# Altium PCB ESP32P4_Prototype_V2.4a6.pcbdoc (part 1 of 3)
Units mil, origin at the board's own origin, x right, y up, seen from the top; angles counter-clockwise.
Board outline 8474.8 x 7265.9 mil, 6 copper layers (Top Layer, GND, VCC, VCC1, GND1, Bottom Layer), stack 62.3 mil thick; 189 components, 155 nets, 775 pads, 406 vias.
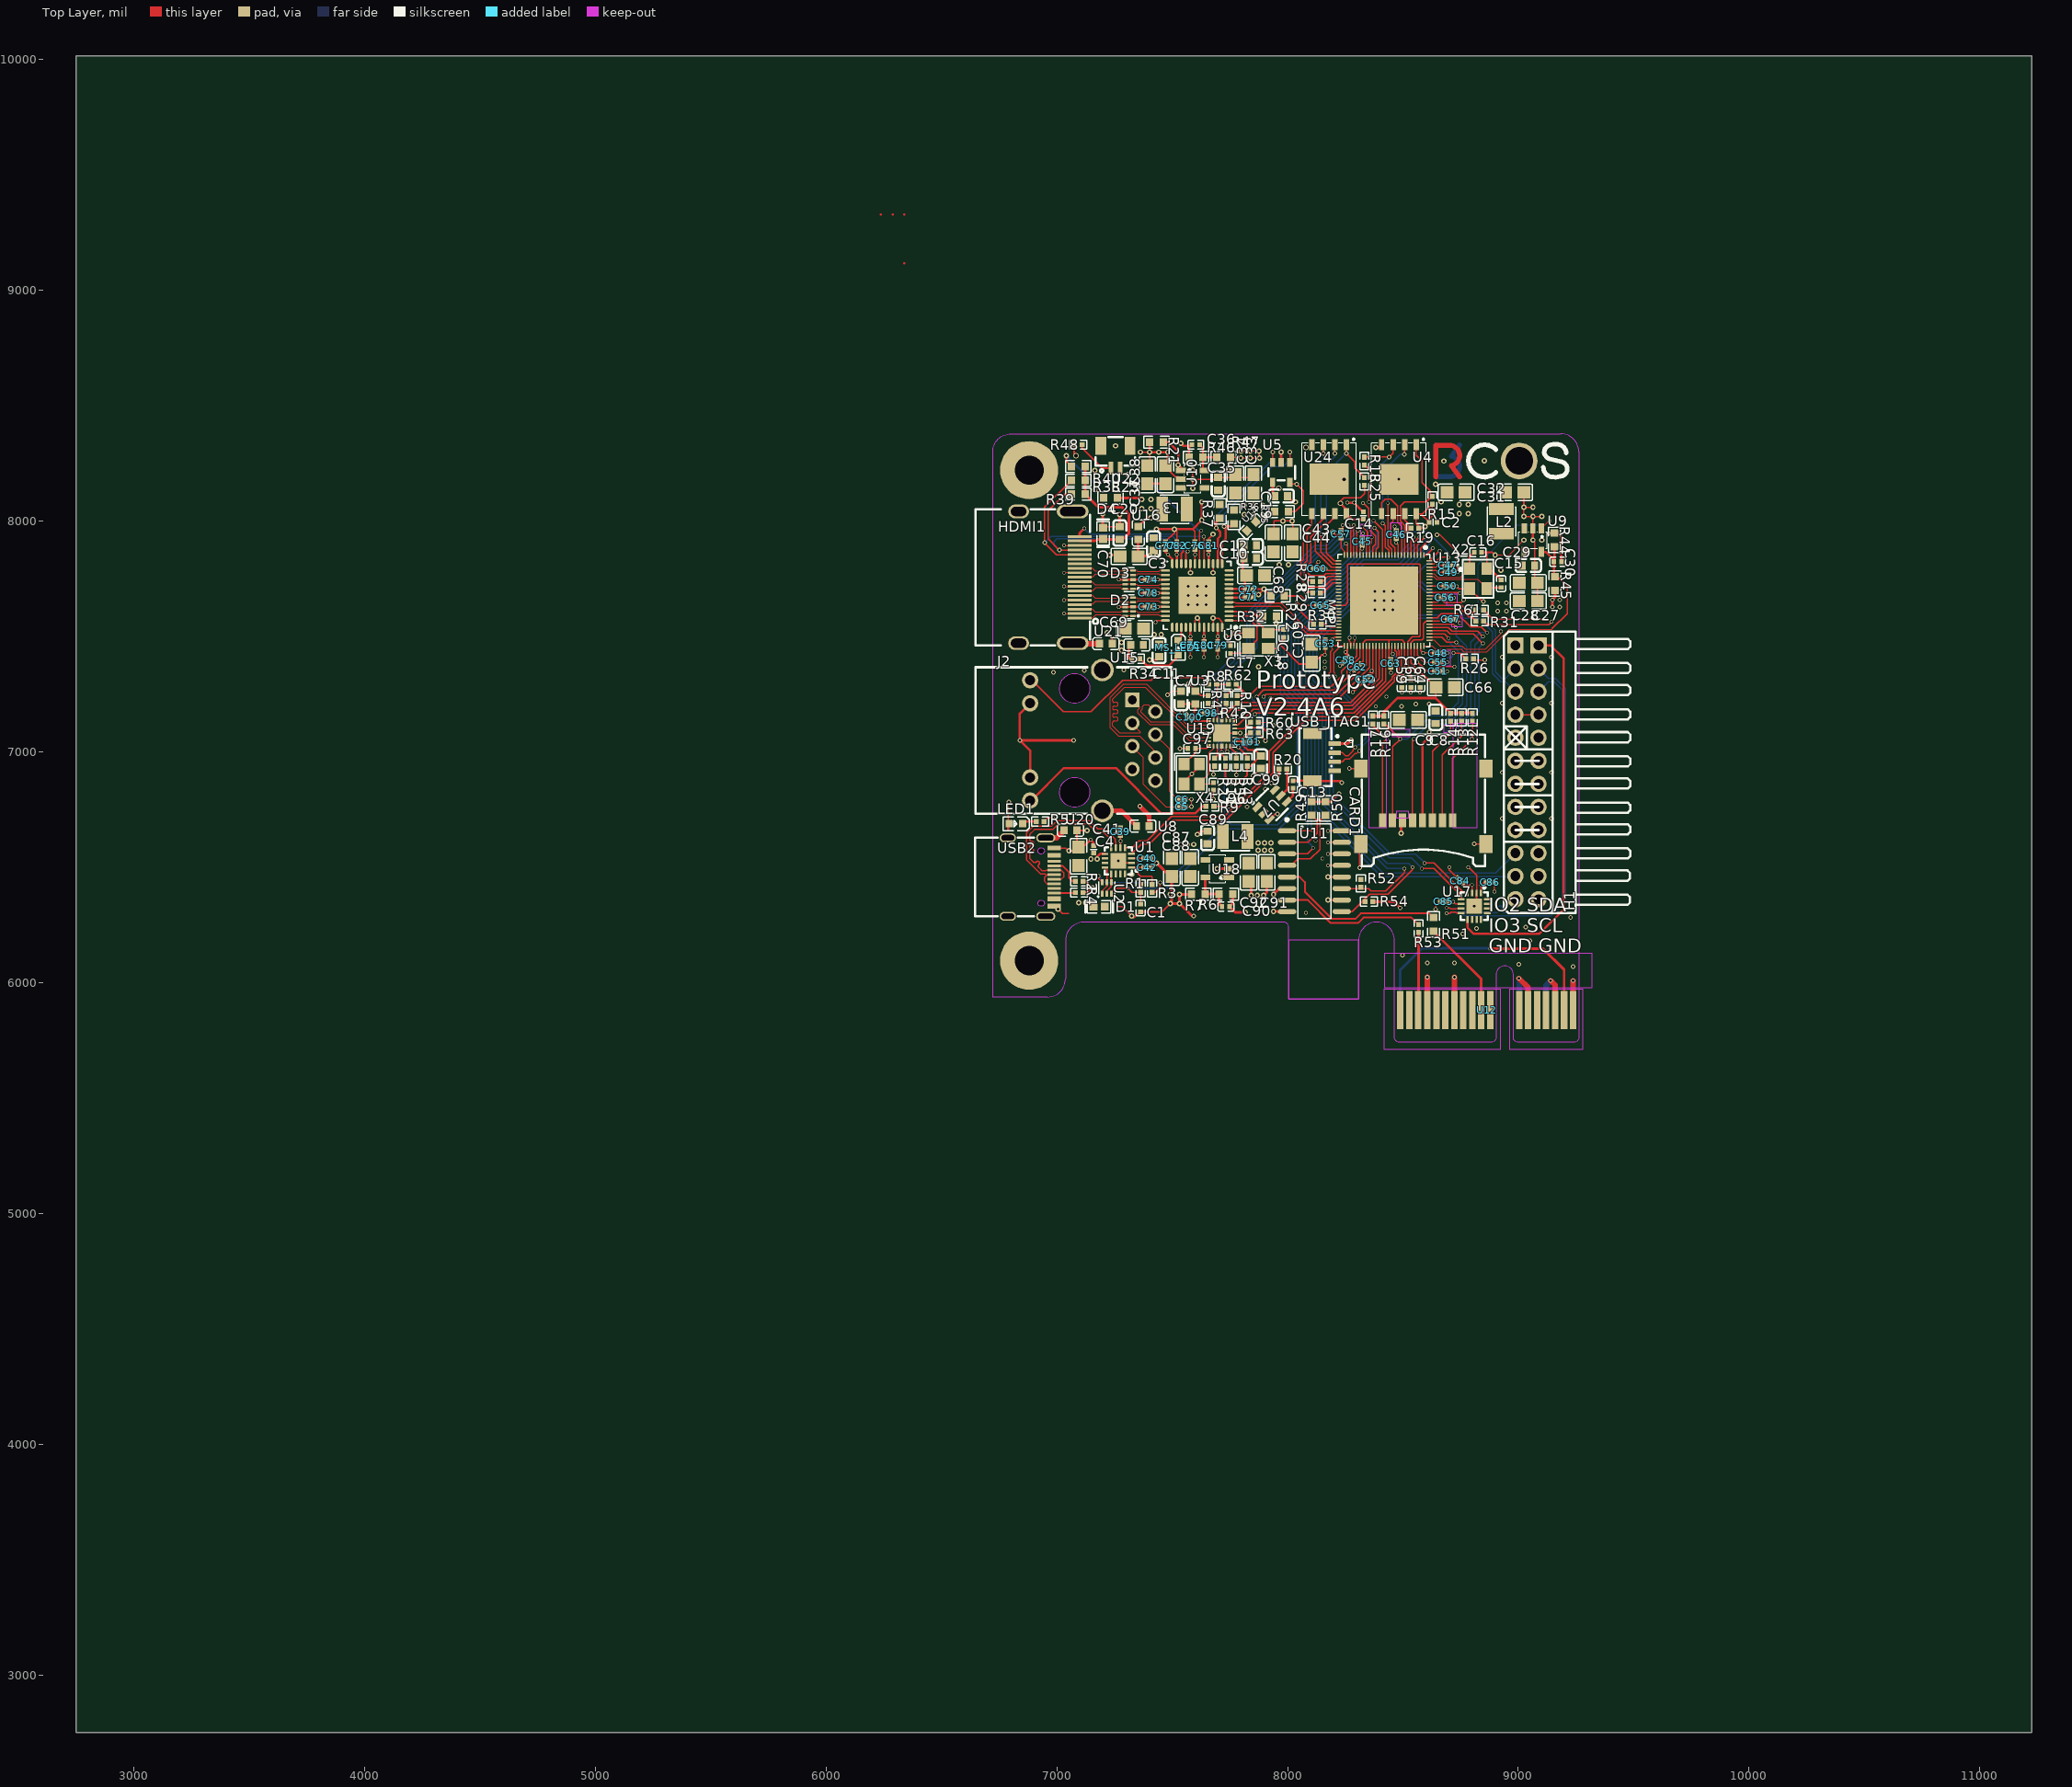
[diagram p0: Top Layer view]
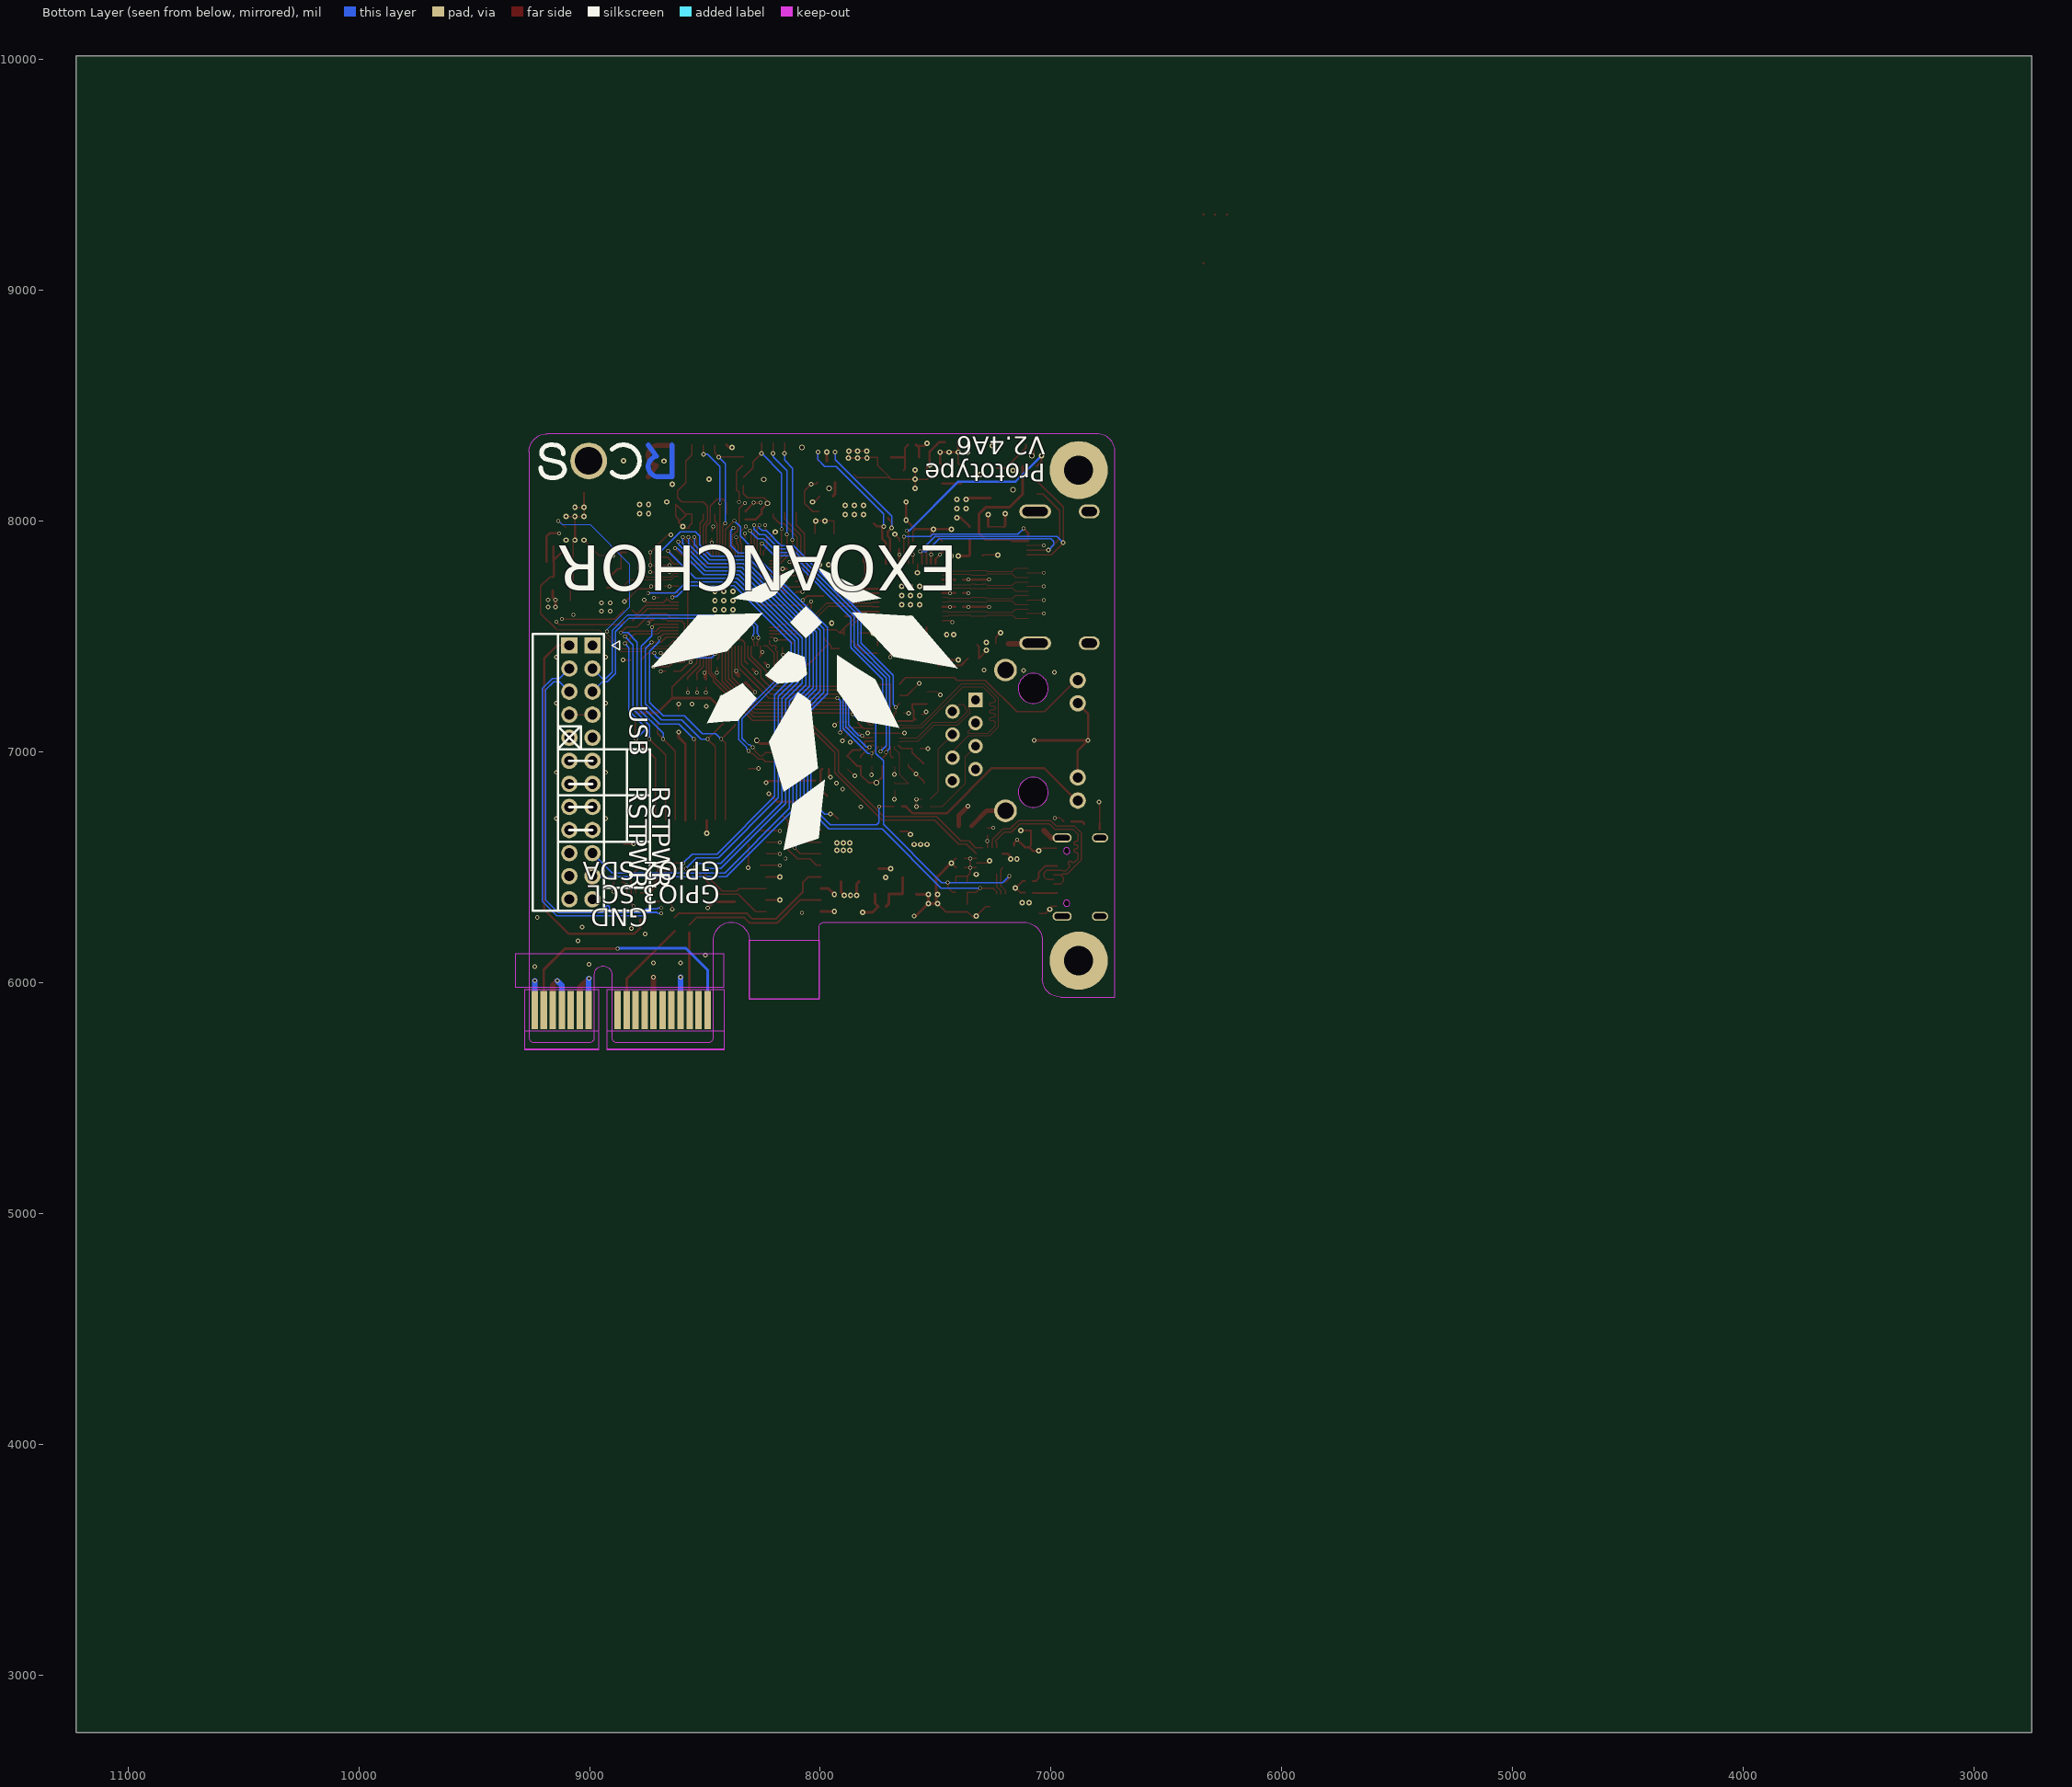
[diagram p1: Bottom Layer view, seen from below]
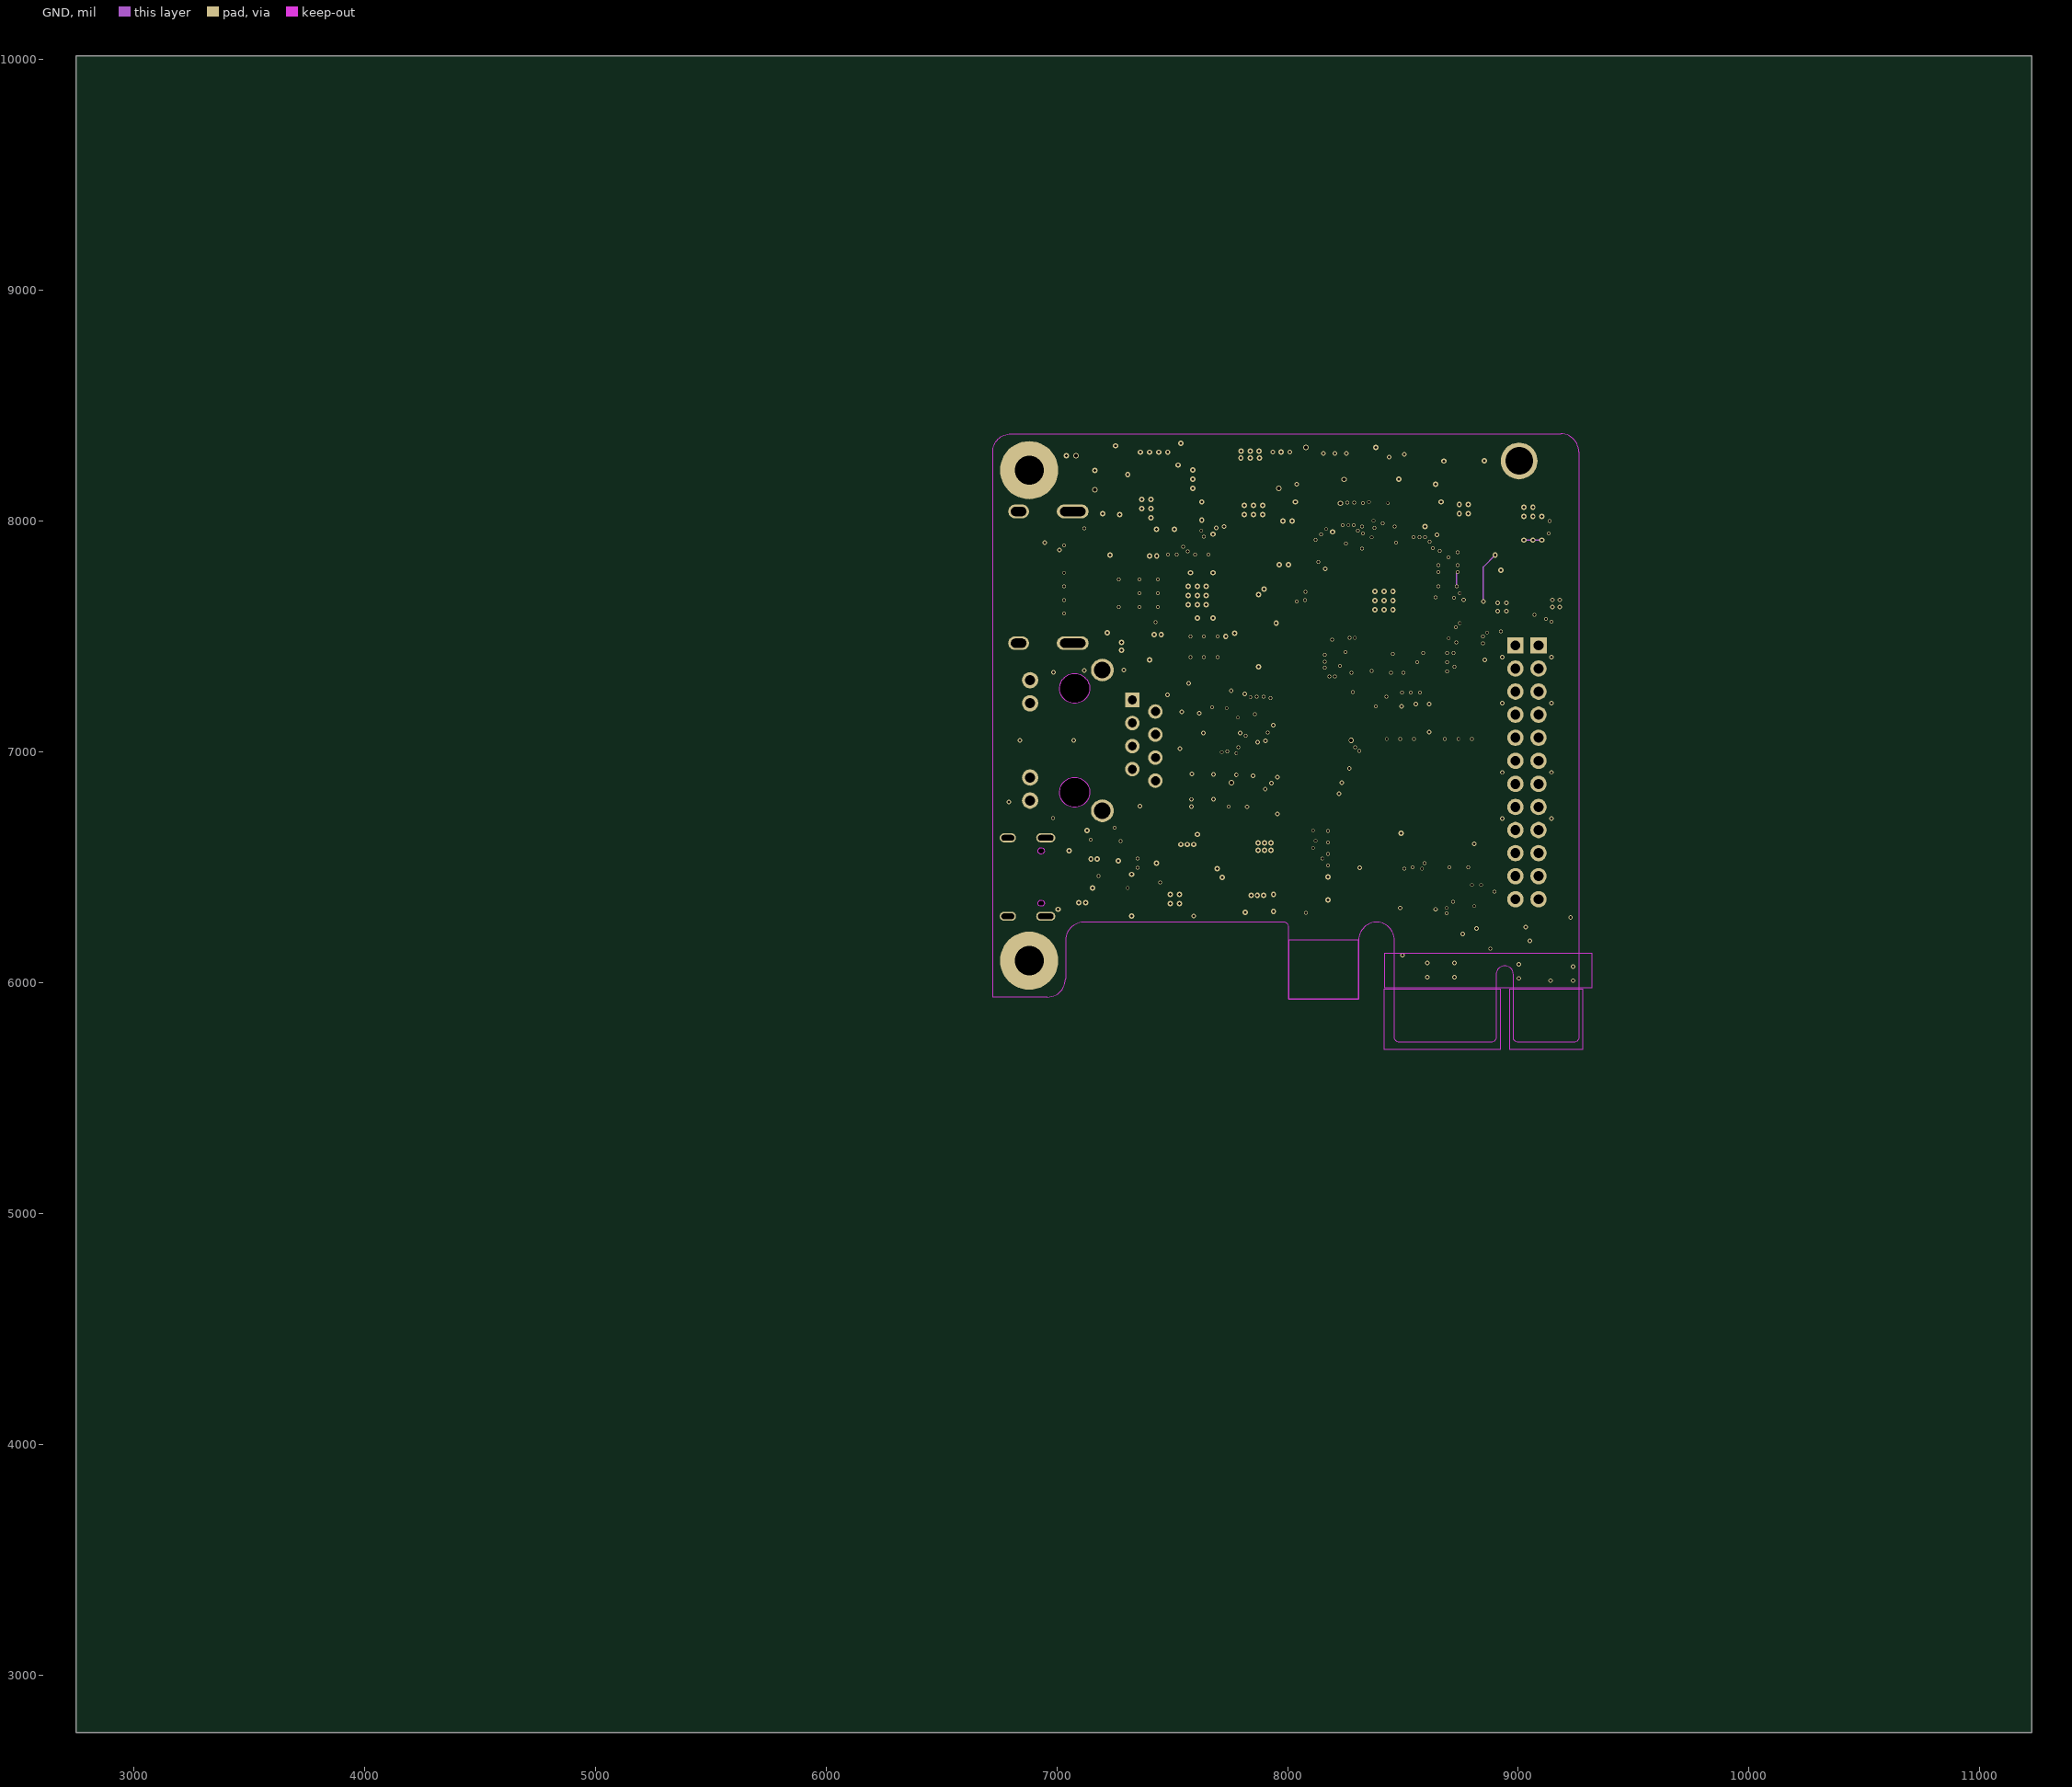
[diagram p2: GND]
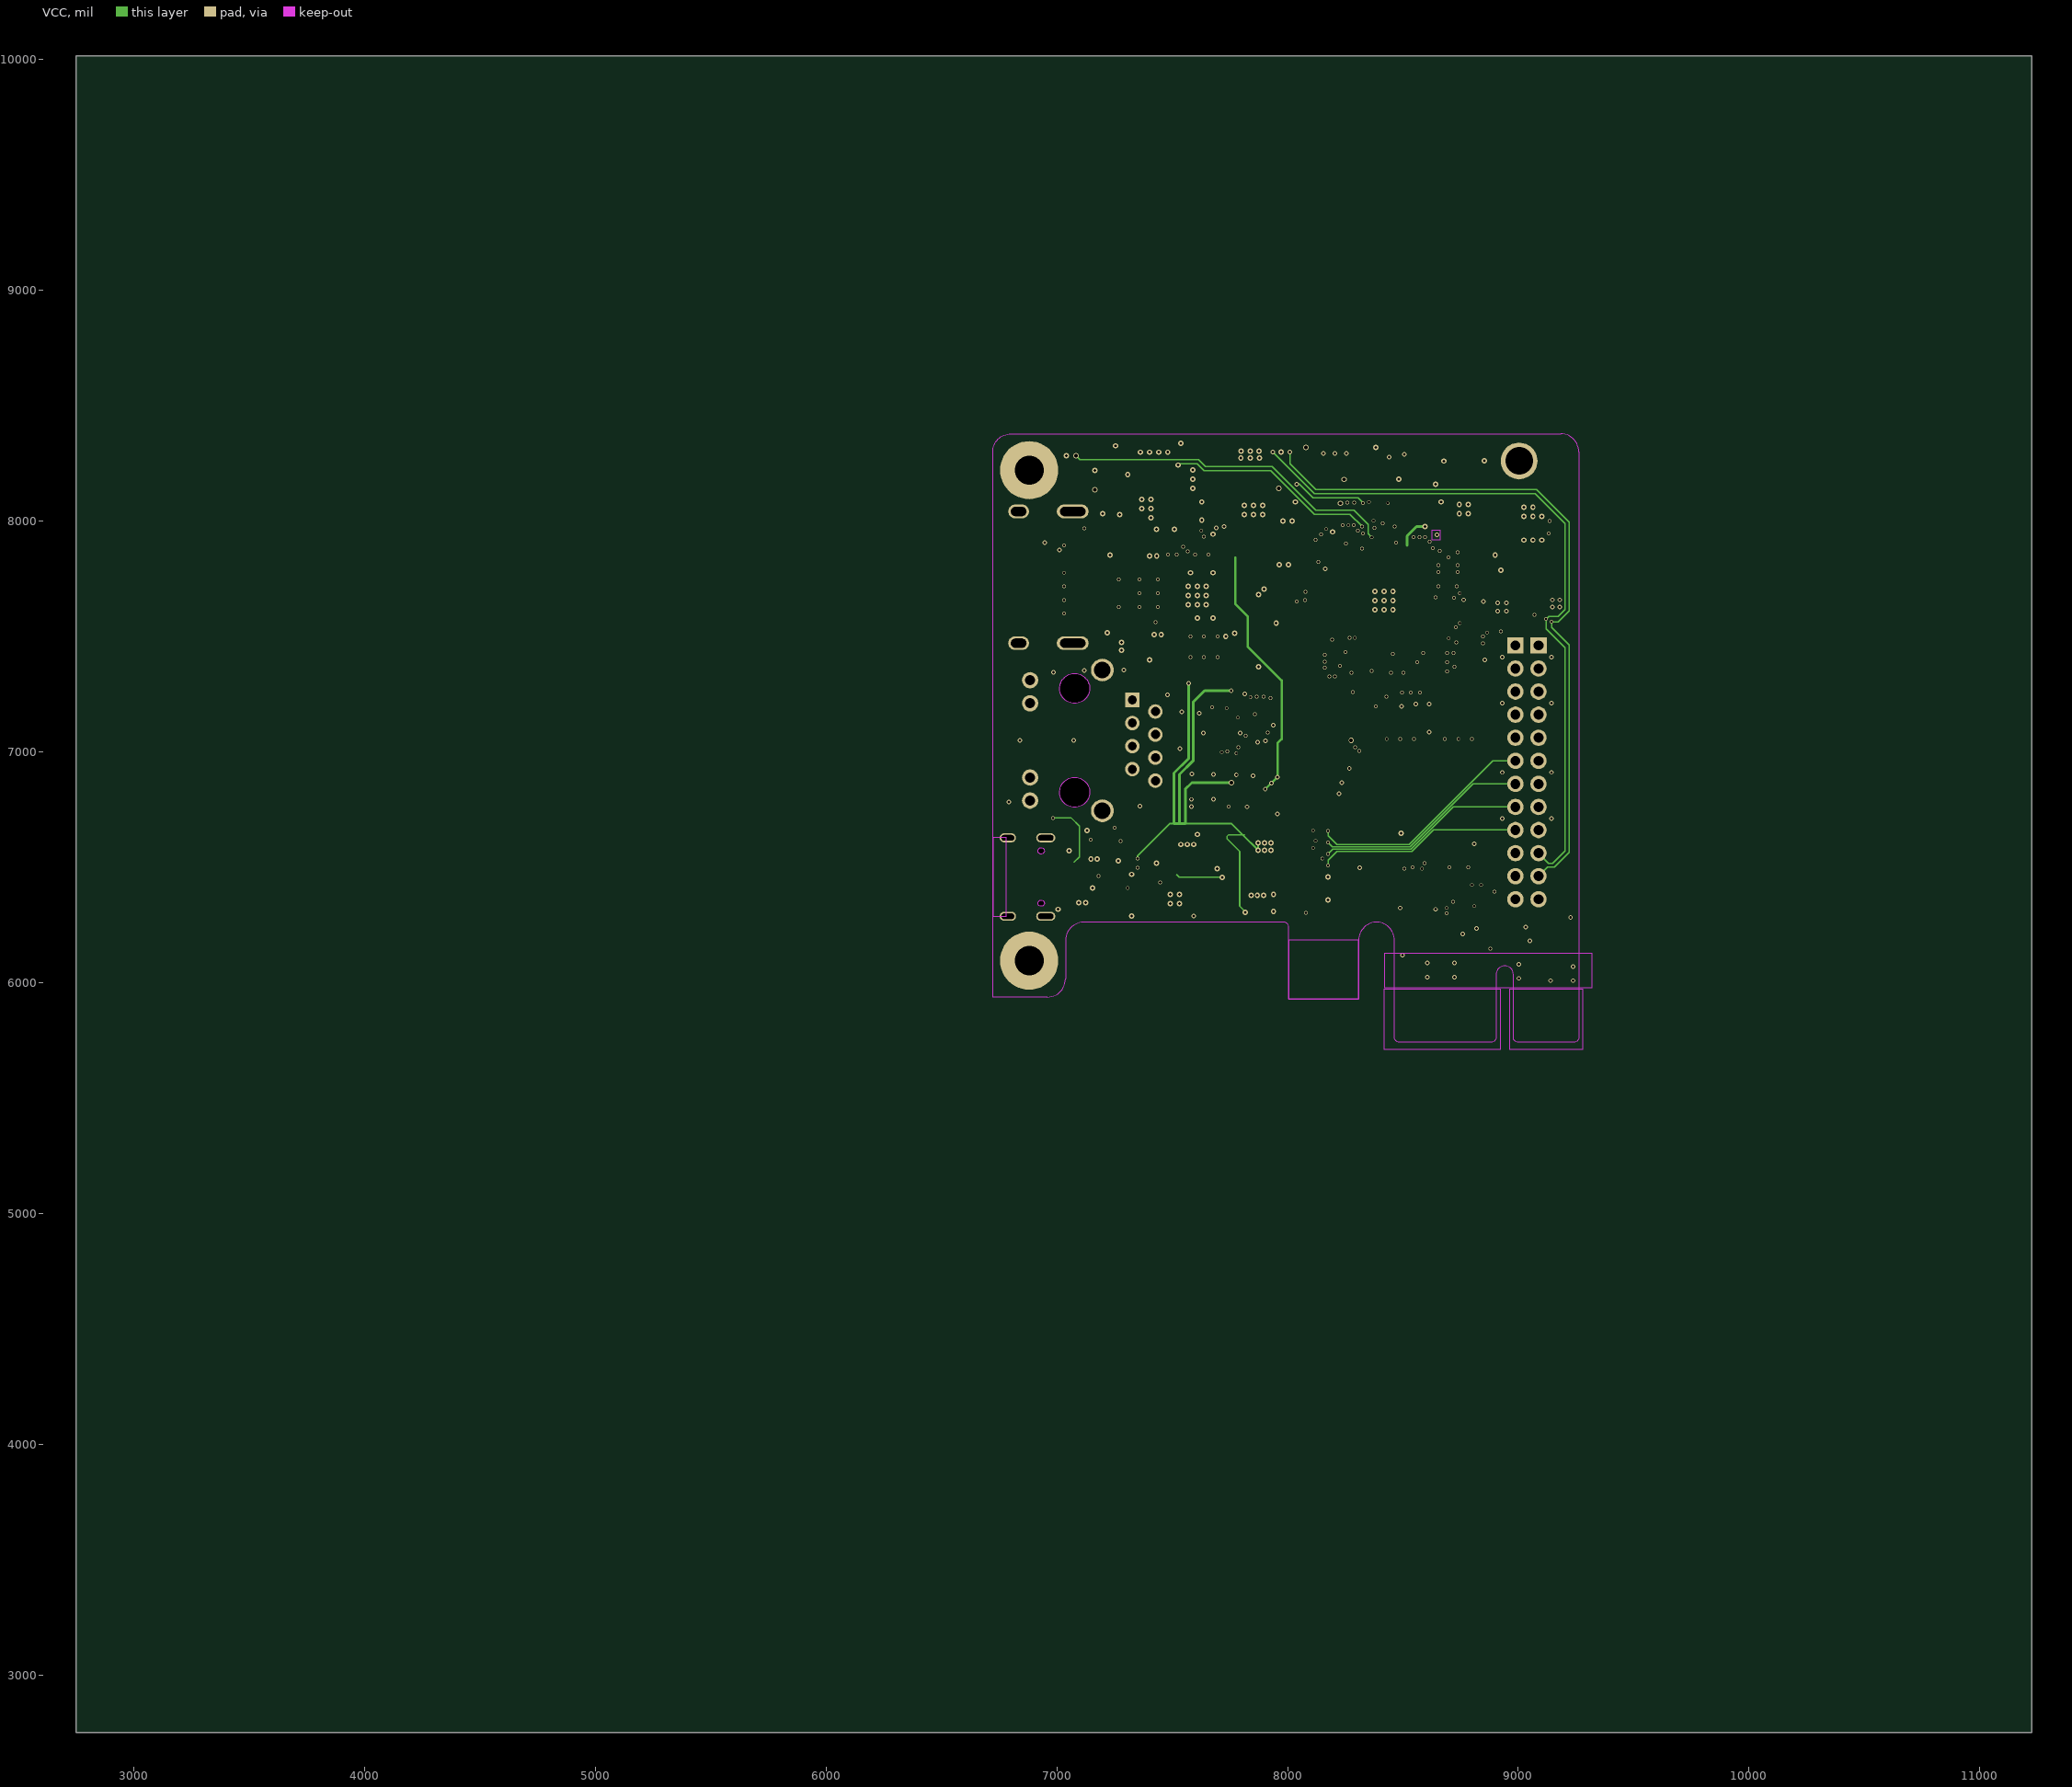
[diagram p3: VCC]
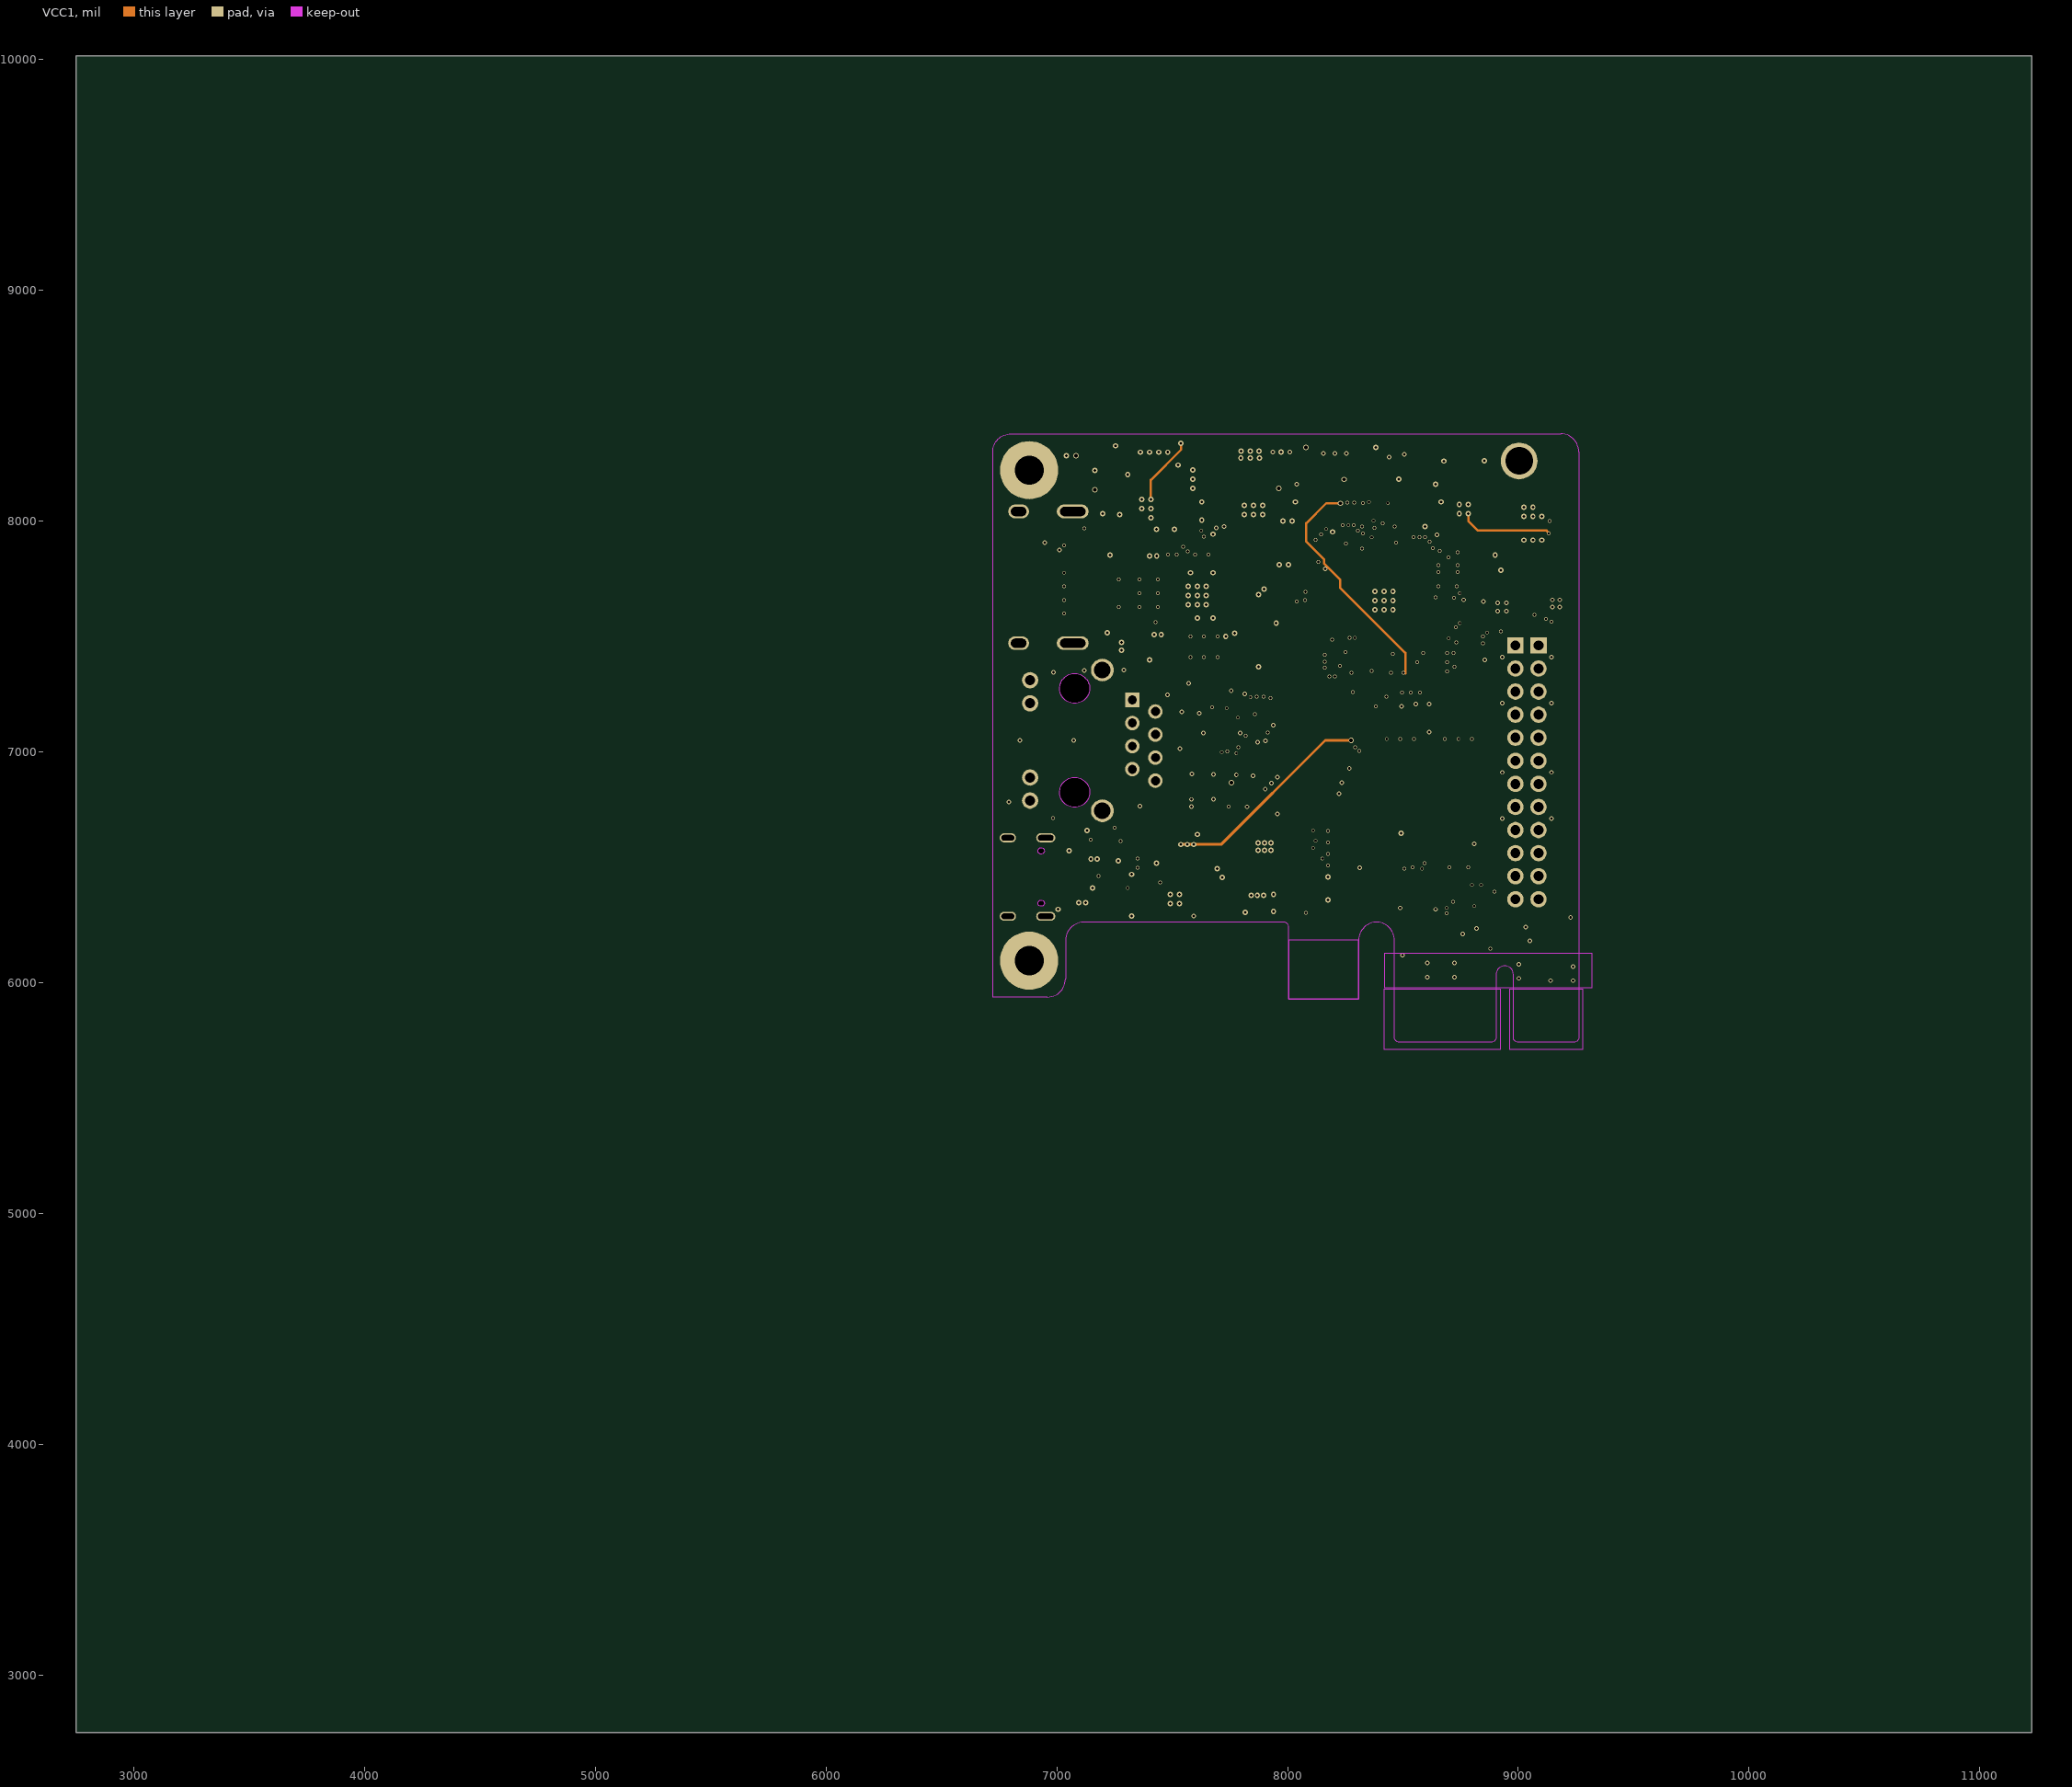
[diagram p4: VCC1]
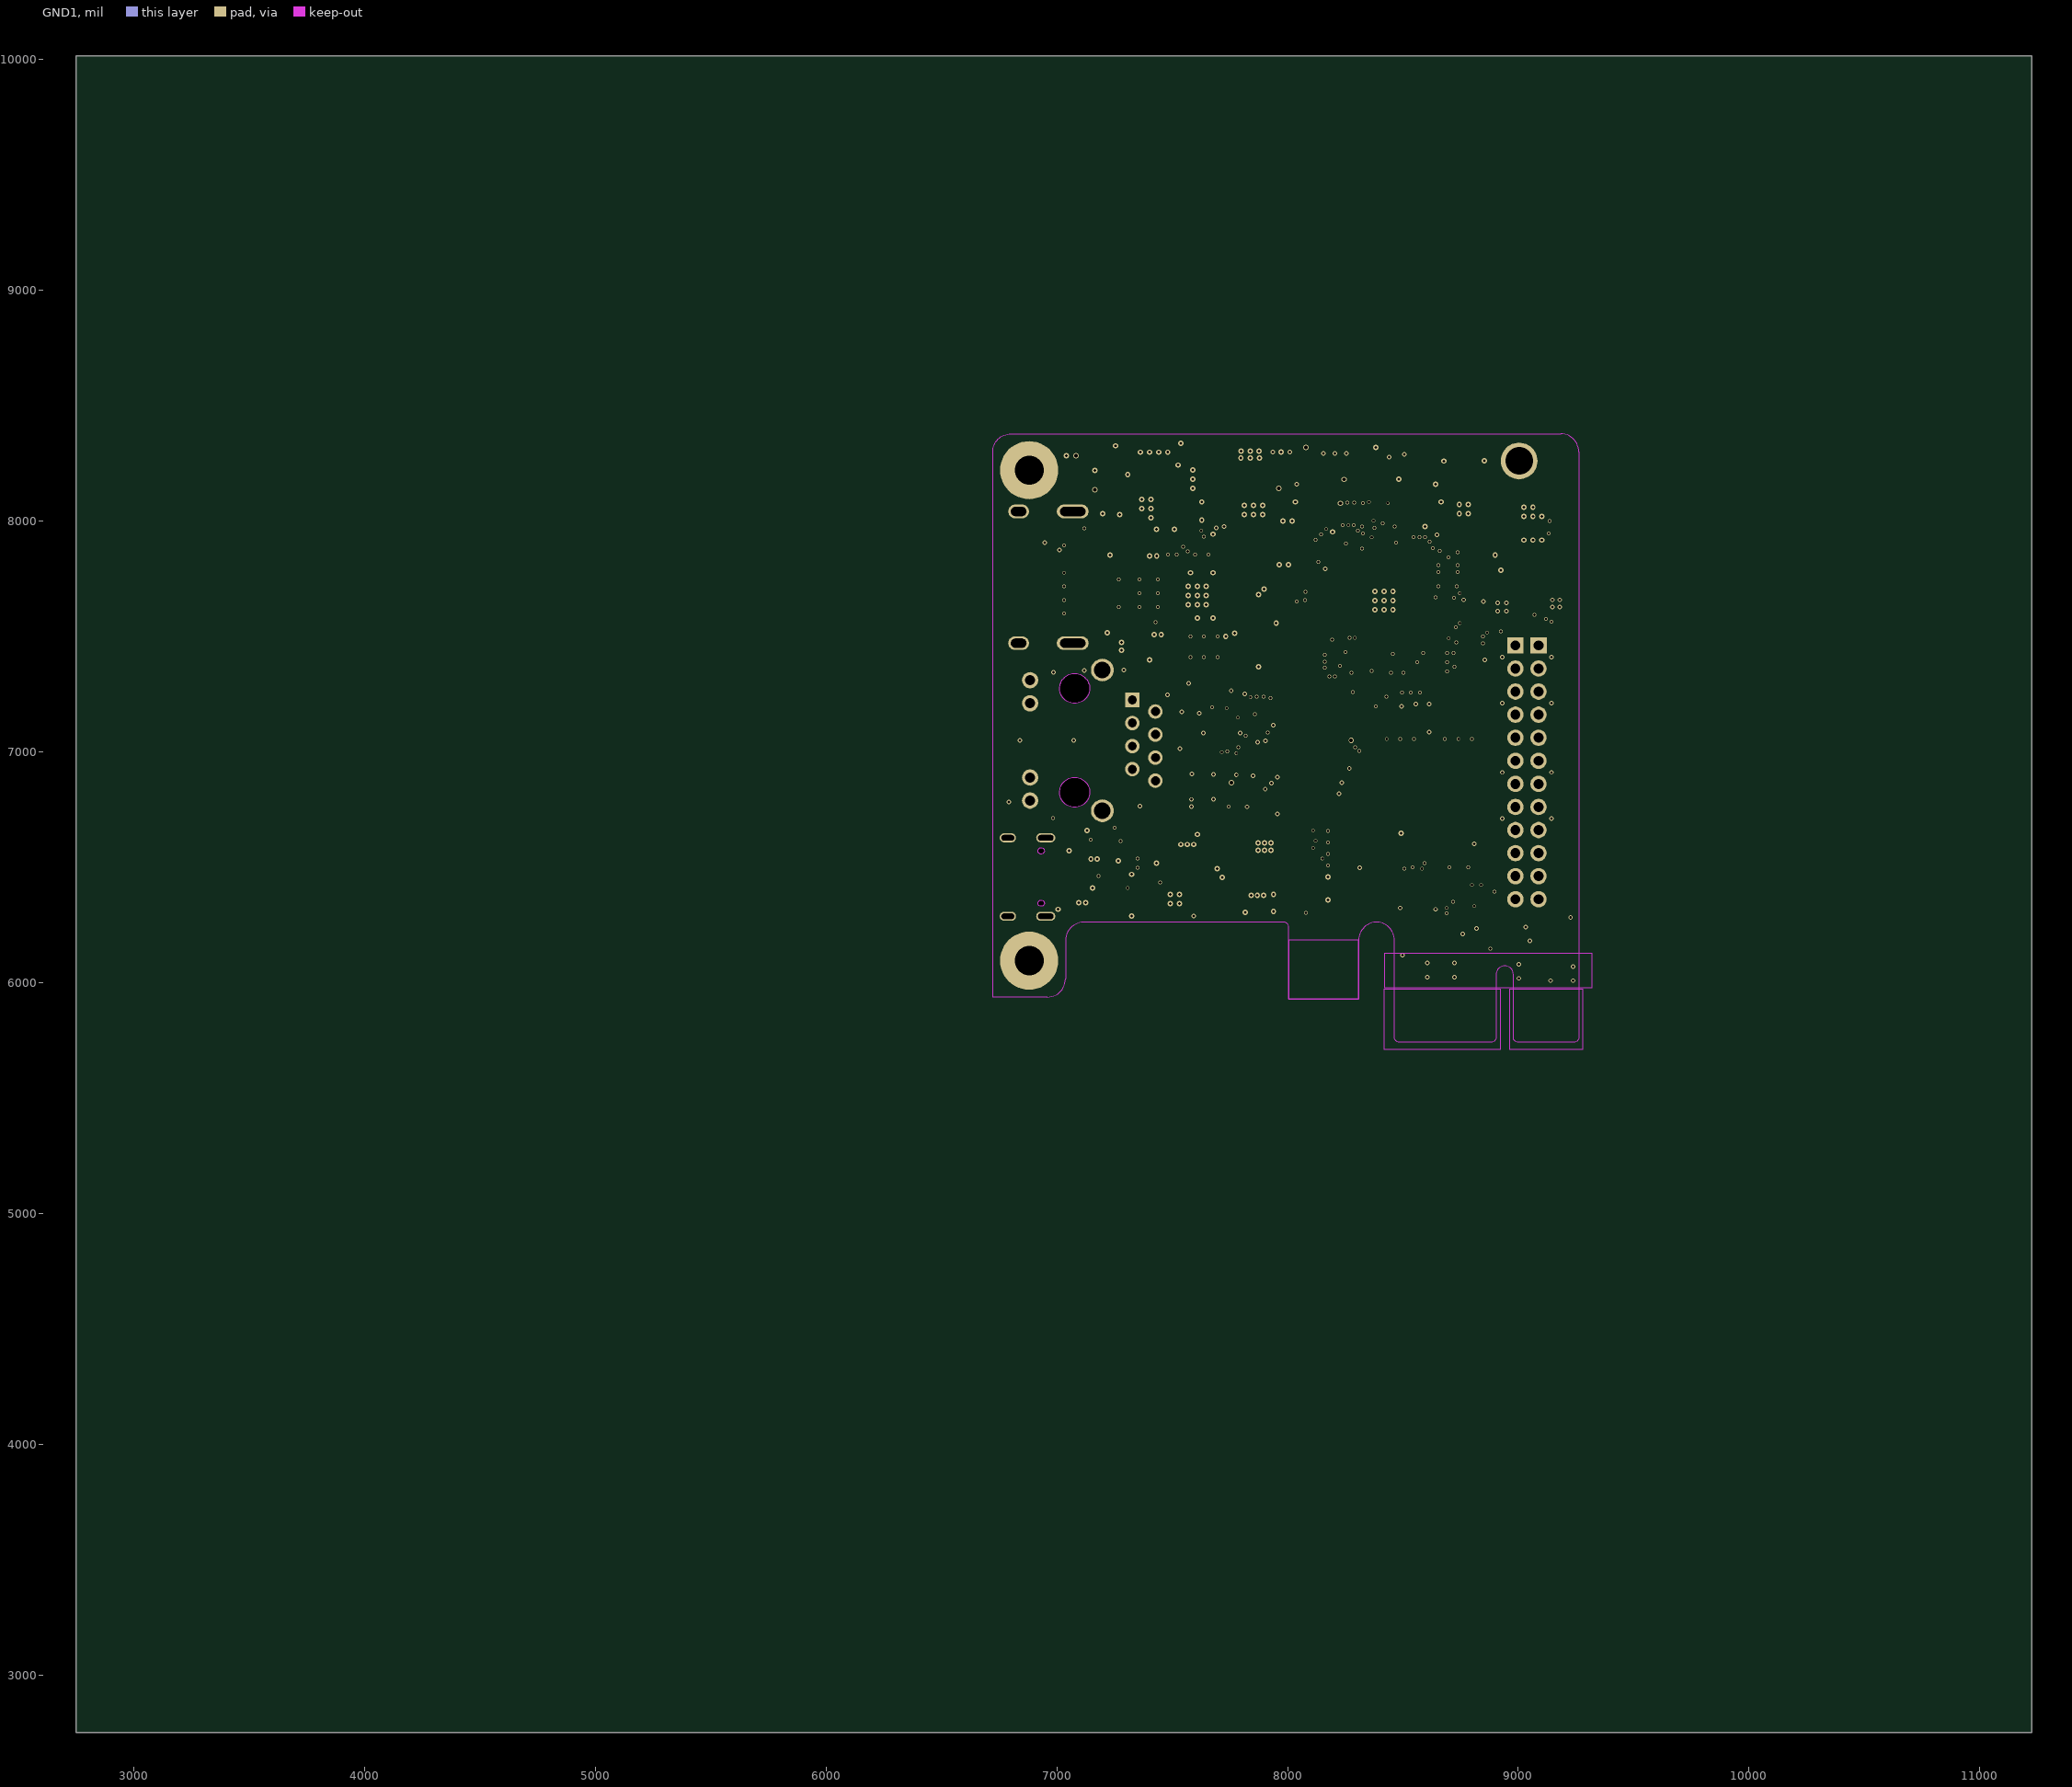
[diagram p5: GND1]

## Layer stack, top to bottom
Top Layer: signal copper 1.4
Dielectric1: surface 3.9, 3313 RC57% 4.2mil, Dk 0
GND: signal copper 1.4
Dielectric2: surface 21.7, 0.55mm H/H No copper, Dk 0
VCC: signal copper 1.4
Dielectric3: surface 4.3, 2116 RC54% 4.9mil, Dk 0
VCC1: signal copper 0.6
Dielectric4: surface 21.7, 0.55mm H/H No copper, Dk 0
GND1: signal copper 0.6
Dielectric5: surface 3.9, 3313 RC57% 4.2mil, Dk 0
Bottom Layer: signal copper 1.4

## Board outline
11224.8,2750 2750,2750 2750,10015.9 11224.8,10015.9

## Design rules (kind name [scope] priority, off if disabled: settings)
BoardOutlineClearance copperThickness1oz [All] p0: genericclearance=10 ignorepadtopadclearanceinfootprint=FALSE except(0: Arc-SplitContinuation Track-SplitContinuation SMDPad-SplitContinuation THPad-SplitContinuation Via-SplitContinuation Fill-SplitContinuation Poly-SplitContinuation Region-SplitContinuation Text-SplitContinuation)
BoardOutlineClearance copperThickness2oz [All] p0: genericclearance=10 ignorepadtopadclearanceinfootprint=FALSE except(0: Arc-SplitContinuation Track-SplitContinuation SMDPad-SplitContinuation THPad-SplitContinuation Via-SplitContinuation Fill-SplitContinuation Poly-SplitContinuation Region-SplitContinuation Text-SplitContinuation)
BoardOutlineClearance copperThicknessInner0.5oz [All] p0: genericclearance=10 ignorepadtopadclearanceinfootprint=FALSE except(0: Arc-SplitContinuation Track-SplitContinuation SMDPad-SplitContinuation THPad-SplitContinuation Via-SplitContinuation Fill-SplitContinuation Poly-SplitContinuation Region-SplitContinuation Text-SplitContinuation)
BoardOutlineClearance Copper_1 [All] p0: genericclearance=10 ignorepadtopadclearanceinfootprint=FALSE except(0: Arc-SplitContinuation Track-SplitContinuation SMDPad-SplitContinuation THPad-SplitContinuation Via-SplitContinuation Fill-SplitContinuation Poly-SplitContinuation Region-SplitContinuation Text-SplitContinuation)
BoardOutlineClearance Copper_copperRegion [All] p0: genericclearance=10 ignorepadtopadclearanceinfootprint=FALSE except(0: Arc-SplitContinuation Track-SplitContinuation SMDPad-SplitContinuation THPad-SplitContinuation Via-SplitContinuation Fill-SplitContinuation Poly-SplitContinuation Region-SplitContinuation Text-SplitContinuation)
BoardOutlineClearance Plane_innerPlane [All] p0: genericclearance=10 ignorepadtopadclearanceinfootprint=FALSE except(0: Arc-SplitContinuation Track-SplitContinuation SMDPad-SplitContinuation THPad-SplitContinuation Via-SplitContinuation Fill-SplitContinuation Poly-SplitContinuation Region-SplitContinuation Text-SplitContinuation)
BoardOutlineClearance otherClearance [All] p0: genericclearance=10 ignorepadtopadclearanceinfootprint=FALSE except(0: Arc-SplitContinuation Track-SplitContinuation SMDPad-SplitContinuation THPad-SplitContinuation Via-SplitContinuation Fill-SplitContinuation Poly-SplitContinuation Region-SplitContinuation Text-SplitContinuation)
Clearance copperThickness1oz [All] p1: gap=7 ignorepadtopadclearanceinfootprint=FALSE
Clearance copperThickness2oz [All] p1: gap=7 ignorepadtopadclearanceinfootprint=FALSE
Clearance copperThicknessInner0.5oz [All] p1: gap=7 ignorepadtopadclearanceinfootprint=FALSE
Clearance Copper_1 [All] p1: gap=7 ignorepadtopadclearanceinfootprint=FALSE
Clearance Copper_copperRegion [All] p1: gap=7 ignorepadtopadclearanceinfootprint=FALSE
Clearance Plane_innerPlane [All] p1: gap=7 ignorepadtopadclearanceinfootprint=FALSE
Clearance otherClearance [All] p1: gap=7 ignorepadtopadclearanceinfootprint=FALSE
DiffPairsRouting differentialPair [All] p1: maxuncoupledlength=10 minlimit=5.9843 maxlimit=Infinity mostfreqgap=8 toplayer_minwidth=4 toplayer_prefwidth=4.7 toplayer_maxwidth=10 bottomlayer_minwidth=4 bottomlayer_prefwidth=4.7 bottomlayer_maxwidth=10 midlayer1_minwidth=4 midlayer1_prefwidth=4.7 midlayer1_maxwidth=10 midlayer2_minwidth=4 midlayer2_prefwidth=4.7 midlayer2_maxwidth=10 midlayer3_minwidth=4 midlayer3_prefwidth=4.7 midlayer3_maxwidth=10 midlayer4_minwidth=4 midlayer4_prefwidth=4.7 midlayer4_maxwidth=10
PasteMaskExpansion pasteMaskExpansion [All] p1: expansion=0
PlaneConnect innerPlane [All] p1: planeconnectstyle=Relief reliefexpansion=20 reliefentries=4 reliefconductorwidth=10 reliefairgap=10
PolygonConnect 1 [All] p1: connectstyle=Direct reliefentries=4 reliefconductorwidth=10 polygonreliefangle="90 Angle" airgapwidth=10
PolygonConnect copperRegion [All] p1: connectstyle=Direct reliefentries=4 reliefconductorwidth=10 polygonreliefangle="90 Angle" airgapwidth=10
RoutingVias viaSize [All] p1: viastyle="Through Hole" holewidth=12.0078 minholewidth=7.874 maxholewidth=248.0316 width=12.0078 minwidth=7.874 maxwidth=248.0316
SolderMaskExpansion solderMaskExpansion [IsVia] p1: useseparateexpansions=TRUE expansion=-1000 expansionbottom=-1000
SolderMaskExpansion solderMaskExpansion [All] p2: useseparateexpansions=TRUE expansion=2.0079 expansionbottom=2.0079
Width copperThickness1oz [All] p1: maxlimit=100 minlimit=4 preferedwidth=10
Width copperThickness0.5oz [All] p1: maxlimit=100 minlimit=4 preferedwidth=10
Width copperThickness2oz [All] p1: maxlimit=100 minlimit=8 preferedwidth=10

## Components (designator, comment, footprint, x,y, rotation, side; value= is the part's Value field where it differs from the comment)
C1 "1uF" C0402#1 7362.6,6323.7 r90 top
C2 "100nF" "C0402 去耦电容"#1 8630.5,7995.3 r0 top
C3 "1uF" C0603#1 7419.4,7900.4 r270 top
C4 "4.7uF" C0805#1 7094.6,6548 r90 top
C5 "100nF" "C0402 去耦电容"#1 7541.5,6762.5 r180 top
C6 "100nF" "C0402 去耦电容"#1 7541.5,6794 r180 top
C7 "1uF" C0603#2 7538.5,7235.5 r270 top
C8 "100nF" C0603#1 8641.9,7150.4 r270 top
C9 "10uF" C0805#2 8523.8,7138.5 r0 top
C10 "1uF" C0603#2 7837.7,7839 r180 top
C11 "1uF" C0603#1 7443.1,7439.7 r90 top
C12 "1uF" C0603#2 7837.7,7894.9 r180 top
C13 "1nF" C0402#1 8023.7,6858.4 r270 top
C14 "100nF" "C0402 去耦电容"#1 8328.9,8024.4 r90 top
C15 "22pF" C0402#1 8925.3,7729.1 r90 top
C16 "22pF" C0402#2 8825,7864.9 r180 top
C17 "22pF" C0402#1 7752.6,7443.7 r90 top
C18 "22pF" C0402#1 7982.6,7513.7 r270 top
C19 "100nF" C0603#2 7972.6,8109 r180 top
C20 "100nF" C0603#2 7272.6,7948.7 r270 top
C27 "10uF" C0805#1 9043.5,7654.2 r180 top
C28 "10uF" C0805#1 9043.5,7732.9 r180 top
C29 "100nF" C0603#2 9043.5,7807.7 r180 top
C30 "22pF" C0402#1 9171.1,7824.1 r0 top
C31 "10uF" C0805#1 8984.4,8124.8 r180 top
C32 "10uF" C0805#2 8730.5,8124.8 r0 top
C33 "10uF" C0805#3 7852.5,8162.2 r270 top
C34 "10uF" C0805#3 7773.8,8162.2 r270 top
C35 "100nF" C0603#1 7699,8162.2 r270 top
C36 "22pF" C0402#3 7602.5,8331.5 r180 top
C37 "10uF" C0805#2 7470.6,8201.5 r270 top
C38 "10uF" C0805#2 7391.9,8201.5 r270 top
C39 "100nF" "C0402 去耦电容"#2 7275.7,6654.3 r270 top
C40 "100nF" "C0402 去耦电容"#3 7391.9,6538.2 r180 top
C41 "100nF" "C0402 去耦电容"#1 7159.6,6577.5 r270 top
C42 "100nF" "C0402 去耦电容"#3 7391.9,6498.8 r180 top
C43 "10uF" C0805#3 8021.8,7906.3 r270 top
C44 "10uF" C0805#3 7939.1,7906.3 r270 top
C45 "100nF" "C0402 去耦电容"#3 8323,7912.2 r270 top
C46 "100nF" "C0402 去耦电容"#2 8470.6,7941.7 r270 top
C47 "100nF" "C0402 去耦电容"#3 8697.3,7808.7 r180 top
C48 "100nF" "C0402 去耦电容"#2 8652.6,7428.1 r180 top
C49 "100nF" "C0402 去耦电容"#3 8697.3,7779.2 r180 top
C50 "100nF" "C0402 去耦电容"#1 8693.3,7718.2 r180 top
C51 "100nF" "C0402 去耦电容"#2 8652.6,7349.4 r180 top
C52 "100nF" "C0402 去耦电容"#2 8337.6,7313.7 r45 top
C53 "100nF" "C0402 去耦电容"#1 8163.5,7469.3 r90 top
C55 "100nF" "C0402 去耦电容"#2 8652.6,7388.7 r180 top
C56 "100nF" "C0402 去耦电容"#2 8682.6,7668.7 r180 top
C57 "100nF" "C0402 去耦电容"#2 8232.6,7943.7 r270 top
C58 "100nF" "C0402 去耦电容"#2 8252.1,7398.4 r45 top
C59 "1uF" C0402#2 8495.5,7296 r90 top
C60 "100nF" "C0402 去耦电容"#2 8128.1,7794.1 r0 top
C61 "1uF" C0402#2 8534.9,7296 r90 top
C62 "100nF" "C0402 去耦电容"#2 8302.6,7368.7 r45 top
C63 "100nF" "C0402 去耦电容"#2 8447.6,7383.7 r90 top
C64 "1uF" C0402#2 8574.2,7296 r90 top
C65 "100nF" "C0402 去耦电容"#1 8142.2,7635.5 r0 top
C66 "10uF" C0805#2 8683.2,7280.3 r180 top
C67 "100nF" "C0402 去耦电容"#1 8707.3,7574.8 r180 top
C68 "4.7uF" C0805#1 7861.3,7765.1 r180 top
C69 "10uF" C0805#2 7336.8,7534.2 r0 top
C70 "4.7uF" C0805#3 7313.1,7847.2 r0 top
C71 "100nF" "C0402 去耦电容"#2 7832.6,7670 r180 top
C72 "100nF" "C0402 去耦电容"#3 7832.1,7705.5 r180 top
C73 "100nF" "C0402 去耦电容"#2 7397.6,7628.7 r0 top
C74 "100nF" "C0402 去耦电容"#1 7397.8,7746.8 r0 top
C75 "100nF" "C0402 去耦电容"#3 7578.9,7461.4 r90 top
C76 "100nF" "C0402 去耦电容"#1 7598.6,7894.4 r270 top
C77 "100nF" "C0402 去耦电容"#1 7470.6,7894.4 r270 top
C78 "100nF" "C0402 去耦电容"#1 7397.8,7687.8 r0 top
C79 "100nF" "C0402 去耦电容"#3 7697,7461.4 r90 top
C80 "100nF" "C0402 去耦电容"#3 7637.9,7461.4 r90 top
C81 "100nF" "C0402 去耦电容"#1 7657.6,7894.4 r270 top
C82 "100nF" "C0402 去耦电容"#1 7519.8,7894.4 r270 top
C84 "100nF" "C0402 去耦电容"#2 8748.2,6441.7 r315 top
C85 "100nF" "C0402 去耦电容"#3 8677.3,6351.1 r0 top
C86 "100nF" "C0402 去耦电容"#2 8878.1,6435.8 r180 top
C87 "4.7uF" C0805#3 7498.1,6498.7 r90 top
C88 "4.7uF" C0805#3 7578.1,6498.7 r90 top
C89 "100nF" C0603#3 7653.1,6628.7 r270 top
C90 "22pF" C0402#2 7732.4,6329.5 r0 top
C91 "10uF" C0805#1 7831.5,6478.2 r90 top
C92 "10uF" C0805#1 7910.2,6478.2 r90 top
C96 "22pF" C0402#2 7678.9,6850.7 r270 top
C97 "22pF" C0402#3 7584.8,7014.5 r0 top
C98 "100nF" "C0402 去耦电容"#1 7655.8,7167.9 r0 top
C99 "1uF" C0603#3 7883.9,6955.5 r90 top
C100 "100nF" "C0402 去耦电容"#4 7573.9,7150.7 r315 top
C101 "100nF" "C0402 去耦电容"#3 7825,7042.1 r180 top
C109 "10uF" C0805#1 8104.5,7427.9 r90 top
CARD1 "XKTF-1307-18" TF-SMD_XKTF-1307-18 8588.7,6764.5 r0 top
D1 "SLPESD0603M05" D0603-BI#1 7183.2,6329.5 r180 top
D2 "TPD4E05U06DQAR" USON-10_L2.5-W1.0-P0.50-BL#1 7313.2,7628.7 r90 top
D3 "TPD4E05U06DQAR" USON-10_L2.5-W1.0-P0.50-BL#2 7313.2,7746.8 r90 top
D4 "SLPESD0603M05" D0603-BI#2 7200.9,7947.6 r270 top
H1 "X6521WR-2x12H-C60D30" HDR-TH_24P-P2.54-H-M-R2-C12-S2.54 9037.6,6911.4 r90 top
HDMI1 "HDMI-001S" HDMI-SMD_HDMI-001S 6966.7,7756.7 r270 top
J2 "HR911105A" RJ45-TH_HR911105A 7155.7,7050 r270 top
L2 "2.2uH" IND-SMD_L3.0-W3.0_FNR30XXS#1 8927,7998.8 r270 top
L3 "2.2uH" IND-SMD_L3.0-W3.0_FNR30XXS#2 7510,8051.9 r0 top
L4 "2.2uH" IND-SMD_L3.0-W3.0_FNR30XXS#2 7773.1,6633.7 r180 top
LED1 "NCD0603R1" LED0603-RD_RED#1 6822.6,6688.7 r180 top
MS_LED1 "NCD0603R1" LED0603-RD_RED#2 7525.7,7451.5 r270 top
R1 "10kΩ" R0402#1 7362.6,6408.7 r270 top
R2 "5.1kΩ" R0402#1 7096.6,6439.7 r180 top
R3 "2.2kΩ" R0402#1 7412.6,6408.7 r270 top
R4 "5.1kΩ" R0402#1 7096.6,6390.5 r180 top
R5 "5.1kΩ" R0402#1 6927.6,6698.7 r180 top
R6 "453kΩ" R0603#1 7733.1,6383.7 r0 top
R7 "100kΩ" R0603#1 7613.1,6383.7 r0 top
R8 "2.2kΩ" R0402#2 7675.8,7292.9 r180 top
R9 "2.2kΩ" R0402#2 7663.9,6763.7 r180 top
R10 "2.49kΩ" R0402#2 7781.6,7227.1 r90 top
R11 "2.2kΩ" R0402#2 7730.5,6955.5 r270 top
R12 "10kΩ" R0402#2 8801.3,7150.4 r270 top
R13 "10kΩ" R0402#2 8754.1,7150.4 r270 top
R14 "10kΩ" R0402#2 8706.8,7150.4 r270 top
R15 "10kΩ" R0402#2 8627.4,8090.9 r90 top
R16 "10kΩ" R0402#3 8417.5,7138.5 r270 top
R17 "10kΩ" R0402#3 8370.2,7138.5 r270 top
R18 "10kΩ" R0402#1 8332.8,8260.6 r90 top
R19 "10kΩ" R0402#3 8551.3,7970.2 r0 top
R20 "22Ω" R0402#2 7980.5,6925.9 r180 top
R21 "100kΩ" R0603#2 7431.3,8343.3 r0 top
R22 "100kΩ" R0603#1 7956.8,7675.9 r0 top
R23 "1kΩ" R0603#1 7232.6,8100.8 r0 top
R25 "10kΩ" R0402#1 8332.8,8172.2 r90 top
R26 "10kΩ" R0402#2 8789.5,7404.3 r0 top
R27 "6.49kΩ" R0402#2 7683.9,6955.5 r270 top
R28 "22Ω" R0402#3 8125.1,7738.7 r0 top
R29 "4.02kΩ" R0402#3 8125.1,7688.7 r0 top
R30 "4.02kΩ" R0402#3 8130.1,7553.7 r0 top
R31 "0Ω" R0402#3 8832.5,7567.5 r180 top
R32 "4.7kΩ" R0603#3 7921.4,7587.4 r180 top
R34 "2.2kΩ" R0402#2 7342.7,7404.3 r180 top
R35 "4.7kΩ" R0603#1 7974.6,8042.1 r180 top
R36 "4.7kΩ" R0603#3 7766.9,8018.8 r90 top
R37 "4.7kΩ" R0603#3 7706.8,8042.6 r90 top
R38 "47kΩ" R0603#2 7092.8,8177.7 r180 top
R39 "47kΩ" R0603#3 7092.6,8118 r180 top
R40 "1kΩ" R0603#2 7092.8,8237 r180 top
R41 "10kΩ" R0402#2 7655.7,7227.1 r90 top
R42 "10kΩ" R0402#2 7734.4,7227.1 r90 top
R43 "2.49kΩ" R0402#2 7825,6955.5 r270 top
R44 "499kΩ" R0603#2 9157,7919.1 r90 top
R45 "499kΩ" R0603#3 9159.3,7729.7 r90 top
R46 "499kΩ" R0603#3 7602.6,8276.3 r180 top
R47 "499kΩ" R0603#3 7722.6,8276.3 r180 top
R48 "22Ω" R0402#2 7092.8,8331.5 r0 top
R49 "510Ω" R0603#1 8104.5,6754.7 r270 top
R50 "510Ω" R0603#1 8163.5,6754.7 r270 top
R51 "510Ω" R0603#2 8632,6252.7 r270 top
R52 "10kΩ" R0402#2 8317.1,6429.9 r270 top
R53 "2.2kΩ" R0402#1 8567.6,6234.4 r270 top
R54 "10kΩ" R0402#3 8352.5,6351.1 r180 top
R59 "2.49kΩ" R0402#2 7777.7,6955.5 r270 top
R60 "2.49kΩ" R0402#1 7856.7,7128.7 r0 top
R61 "0Ω" R0402#3 8832.5,7615 r180 top
R62 "2.49kΩ" R0402#3 7760.8,7292.9 r0 top
R63 "2.49kΩ" R0402#3 7855.8,7082.9 r0 top
U1 "CH343P" TQFN-16_L3.0-W3.0-P0.50-BL-EP1.7#1 7265.9,6528.3 r90 top
U2 "EMH4T2R" SOT-563-6_L1.6-W1.2-P0.50-LS1.6-BL 7216.7,6410.2 r0 top
U3 "BLM18PG121SN1D" L0603#1 7600.8,7235.8 r90 top
U4 "GD5F2GQ5UEYIGR" WSON-8_L6.0-W8.0-P1.27-BL-EP#1 8482.4,8181.9 r180 top
U5 "AT24C16C-STUM-T" SOT-23-5_L2.9-W1.6-P0.95-LS2.8-BL 7972.6,8211.4 r180 top
U6 "MS2109" QFN-48_L7.0-W7.0-P0.50-TL-EP4.1 7608.4,7677.9 r180 top
U7 "TPS22918DBVR" SOT-23-6_L2.9-W1.6-P0.95-LS2.8-BR 7933.2,6772.4 r225 top
U8 "BLM18PG121SN1D" L0603#2 7372.6,6678.7 r180 top
U9 "TLV62569DBVR" SOT-23-5_L3.0-W1.7-P0.95-LS2.8-BR#1 9063.2,7917.9 r90 top
U10 "TLV62569DBVR" SOT-23-5_L3.0-W1.7-P0.95-LS2.8-BR#2 7588.7,8181.9 r180 top
U11 "AQS221R2S" SO-16_L10.3-W4.4-P1.27-LS7.0-BL 8116.3,6483 r270 top
U12 "" "PCIe*1 key" 8488.6,5880.8 r0 top
U13 "ESP32-P4NRW32X" QFN-104_L10.0-W10.0-P0.35-TL-EP7.5 8417.7,7656.2 r270 top
U14 "BLM18PG121SN1D" L0603#3 7843.6,7977.5 r225 top
U15 "BLM18PG121SN1D" L0603#1 7347.6,7463.7 r0 top
U16 "BLM18PG121SN1D" L0603#3 7352.6,7948.7 r270 top
U17 "CH343P" TQFN-16_L3.0-W3.0-P0.50-BL-EP1.7#2 8809.2,6331.5 r180 top
U18 "TLV62569DBVR" SOT-23-5_L3.0-W1.7-P0.95-LS2.8-BR#2 7695.2,6494 r0 top
U19 "DP83825IRMQR" HVQFN-24_L3.0-W3.0-P0.40-TL-EP1.9 7714.7,7081.5 r270 top
U20 "BLM18PG121SN1D" L0603#3 7059.2,6660.2 r180 top
U21 "BLM18PG121SN1D" L0603#1 7212.7,7469.3 r180 top
U22 "ZX-SH1.0-2PLT" CONN-SMD_2P-P1.00_MEGASTAR_ZX-SH1.0-2PLT 7254.1,8278.3 r0 top
U24 "GD25Q127CYIGR" WSON-8_L6.0-W8.0-P1.27-BL-EP#2 8179.9,8181.9 r180 top
USB2 "HX TYPE-C 16P L8.35" USB-C-SMD_HX-TYPE-C-16P-L8.35 6887.9,6457.6 r270 top
USB_JTAG1 "ZX-SH1.0-4PLT" CONN-SMD_4P-P1.00_ZX-SH1.0-4PLN 8155.7,6977 r270 top
X2 "40MHz" OSC-SMD_4P-L3.2-W2.5-BL_SIT8008BI 8826.4,7750.9 r270 top
X3 "24MHz" CRYSTAL-SMD_4P-L3.2-W2.5-BL#1 7873.2,7481.7 r0 top
X4 "25MHz" CRYSTAL-SMD_4P-L3.2-W2.5-BL#2 7584.8,6904.3 r270 top

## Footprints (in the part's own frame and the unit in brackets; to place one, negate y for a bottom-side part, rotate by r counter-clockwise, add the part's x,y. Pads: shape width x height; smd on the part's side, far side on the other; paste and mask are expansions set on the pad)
C0402#1 [mil]
  rect 19.7x21.3 smd: 1(-16.5,0) 2(16.5,0)
  silkscreen extent -34,-20 34,20
C0402#2 [mil]
  rect 19.7x21.3 smd: 1(-16.5,0) 2(16.6,0)
  silkscreen extent -34,-20 34,20
C0402#3 [mil]
  rect 19.7x21.3 smd: 1(-16.6,0) 2(16.5,0)
  silkscreen extent -34,-20 34,20
"C0402 去耦电容"#1 [mil]
  rect 19.7x21.3 smd: 1(-16.6,0) 2(16.5,0)
  silkscreen extent 0,-14 0,14
"C0402 去耦电容"#2 [mil]
  rect 19.7x21.3 smd: 1(-16.5,0) 2(16.5,0)
  silkscreen extent 0,-14 0,14
"C0402 去耦电容"#3 [mil]
  rect 19.7x21.3 smd: 1(-16.5,0) 2(16.6,0)
  silkscreen extent 0,-14 0,14
"C0402 去耦电容"#4 [mil]
  rect 19.7x21.3 smd: 1(-16.55,0) 2(16.48,-0.07)
  silkscreen extent 0,-14 0,14
C0603#1 [mil]
  rect 31.5x35.4 smd: 1(-27.5,0) 2(27.6,0)
  silkscreen extent -55,-28 55,28
C0603#2 [mil]
  rect 31.5x35.4 smd: 1(-27.6,0) 2(27.6,0)
  silkscreen extent -55,-28 55,28
C0603#3 [mil]
  rect 31.5x35.4 smd: 1(-27.6,0) 2(27.5,0)
  silkscreen extent -55,-28 55,28
C0805#1 [mil]
  rect 55.5x53.1 smd paste-3937 mask+2: 1(-39.4,0) 2(39.4,0)
  silkscreen extent -77,-36 77,36
C0805#2 [mil]
  rect 55.5x53.1 smd paste-3937 mask+2: 1(-39.4,0) 2(39.3,0)
  silkscreen extent -77,-36 77,36
C0805#3 [mil]
  rect 55.5x53.1 smd paste-3937 mask+2: 1(-39.3,0) 2(39.4,0)
  silkscreen extent -77,-36 77,36
CONN-SMD_2P-P1.00_MEGASTAR_ZX-SH1.0-2PLT [mil]
  rect 19.7x55.1 smd paste+0 mask+2: 1(-19.7,-48.2) 2(19.7,-48.2)
  rect 47.2x78.7 smd paste+0 mask+2: 3(63,48.2) 4(-63,48.2)
  silkscreen extent -86,-67 86,86
CONN-SMD_4P-P1.00_ZX-SH1.0-4PLN [mil]
  rect 19.7x55.1 smd: 1(-59,48.2) 2(-19.7,48.2) 3(19.7,48.2) 4(59.1,48.2)
  rect 47.2x78.7 smd: 5(102.4,-48.3) 6(-102.4,-48.3)
  silkscreen extent -126,-105 126,65
CRYSTAL-SMD_4P-L3.2-W2.5-BL#1 [mil]
  rect 55.1x47.2 smd: 1(-43.3,-33.5) 2(43.3,-33.5) 3(43.3,33.4) 4(-43.3,33.4)
  silkscreen extent -89,-75 80,66
CRYSTAL-SMD_4P-L3.2-W2.5-BL#2 [mil]
  rect 55.1x47.2 smd: 1(-43.3,-33.5) 2(43.3,-33.5) 3(43.3,33.5) 4(-43.3,33.5)
  silkscreen extent -89,-75 80,66
D0603-BI#1 [mil]
  rect 34.4x35.7 smd paste-3937 mask+2: 1(-24.5,0) 2(24.4,0)
  silkscreen extent -60,-27 60,27
D0603-BI#2 [mil]
  rect 34.4x35.7 smd paste-3937 mask+2: 1(-24.5,0) 2(24.5,0)
  silkscreen extent -60,-27 60,27
HDMI-SMD_HDMI-001S [mil]
  rect 11.8x102.4 smd paste-3937 mask+2: 1(177.2,132.3) 2(157.5,132.3) 3(137.8,132.3) 4(118.1,132.3) 5(98.5,132.3) 6(78.8,132.3) 7(59.1,132.3) 8(39.4,132.3) 9(19.7,132.3) 10(0,132.3) 11(-19.7,132.3) 12(-39.3,132.3) 13(-59,132.3) 14(-78.7,132.3) 15(-98.4,132.3) 16(-118.1,132.3) 17(-137.8,132.3) 18(-157.5,132.3) 19(-177.1,132.3)
  oval 59.1x137.8 hole 39.4 slot 110.2 at 90 deg: 20(-285.4,102.3) 21(285.5,102.3)
  oval 59.1x90.6 hole 39.4 slot 66.9 at 90 deg: 22(-285.4,-132.3) 23(285.5,-132.3)
  silkscreen extent -295,-320 295,212
HDR-TH_24P-P2.54-H-M-R2-C12-S2.54 [mil]
  round 70.9 hole 43.3: 1(-550,-50) 2(-550,50) 3(-450,-50) 4(-450,50) 5(-350,-50) 6(-350,50) 7(-250,-50) 8(-250,50) 9(-150,-50) 10(-150,50) 11(-50,-50) 12(-50,50) 13(50,-50) 14(50,50) 15(150,-50) 16(150,50) 17(250,-50) 18(250,50) 19(350,-50) 20(350,50) 21(450,-50) 22(450,50)
  rect 70.9x70.9 hole 43.3: 23(550,-50) 24(550,50)
  silkscreen extent -610,-448 610,-111
HVQFN-24_L3.0-W3.0-P0.40-TL-EP1.9 [mil]
  oval 20.7x7.9 smd paste-3937 mask+2: 1(-56.5,35.4) 2(-56.5,19.7) 4(-56.5,-19.7) 5(-56.5,-35.4) 13(56.6,-35.4) 14(56.6,-19.7) 16(56.6,19.7) 17(56.6,35.4)
  rect 20.7x15.7 smd paste-3937 mask+2: 3(-56.5,0) 15(56.6,0)
  rect 9.8x9.8 smd paste-3937 mask+2: 6(-52.1,-52.2) 12(52.2,-52.1) 18(52.2,52.2) 24(-52.1,52.2)
  oval 7.9x20.7 smd paste-3937 mask+2: 7(-35.4,-56.6) 8(-19.6,-56.6) 10(19.7,-56.6) 11(35.5,-56.6) 19(35.5,56.6) 20(19.7,56.6) 22(-19.6,56.6) 23(-35.4,56.6)
  rect 15.7x20.7 smd paste-3937 mask+2: 9(0,-56.6) 21(0,56.6)
  rect 74.8x74.8 smd paste-3937 mask+2: 25(0,0)
  silkscreen extent -72,-63 63,63
IND-SMD_L3.0-W3.0_FNR30XXS#1 [mil]
  rect 51.2x107.1 smd: 1(53.2,0) 2(-53.1,0)
  silkscreen extent -62,-62 62,62
IND-SMD_L3.0-W3.0_FNR30XXS#2 [mil]
  rect 51.2x107.1 smd: 1(53.1,0) 2(-53.2,0)
  silkscreen extent -62,-62 62,62
L0603#1 [mil]
  rect 31.5x34 smd paste-3937 mask+2: 1(-27.6,0) 2(27.5,0)
  silkscreen extent -56,-26 56,26
L0603#2 [mil]
  rect 31.5x34 smd paste-3937 mask+2: 1(-27.5,0) 2(27.6,0)
  silkscreen extent -56,-26 56,26
L0603#3 [mil]
  rect 31.5x34 smd paste-3937 mask+2: 1(-27.58,0) 2(27.58,0)
  silkscreen extent -56,-26 56,26
LED0603-RD_RED#1 [mil]
  rect 31.5x31.5 smd: 1(-29.5,-0.1) 2(29.5,0.1)
  silkscreen extent -59,-29 55,30
LED0603-RD_RED#2 [mil]
  rect 31.5x31.5 smd: 1(-31.5,-0.1) 2(31.4,0.2)
  silkscreen extent -59,-29 55,30
OSC-SMD_4P-L3.2-W2.5-BL_SIT8008BI [mil]
  rect 55.1x47.2 smd: 1(-43.4,-37.4) 2(43.3,-37.4) 3(43.3,37.4) 4(-43.4,37.4)
  silkscreen extent -100,-90 83,67
"PCIe*1 key" [mil]
  rect 28x165 smd far side: A1(0,0) A2(39,0) A3(78,0) A4(117,0) A5(156,0) A6(195,0) A7(234,0) A8(273,0) A9(312,0) A10(351,0) A11(390,0) A12(515,0) A13(554,0) A14(593,0) A15(632,0) A16(671,0) A17(710,0) A18(749,0)
  rect 28x165 smd: B1(0,0) B2(39,0) B3(78,0) B4(117,0) B5(156,0) B6(195,0) B7(234,0) B8(273,0) B9(312,0) B10(351,0) B11(390,0) B12(515,0) B13(554,0) B14(593,0) B15(632,0) B16(671,0) B17(710,0) B18(749,0)
QFN-48_L7.0-W7.0-P0.50-TL-EP4.1 [mil]
  oval 39.4x11 smd paste+0 mask+2: 1(-137.8,108.2) 2(-137.8,88.6) 3(-137.8,68.9) 4(-137.8,49.2) 5(-137.8,29.5) 6(-137.8,9.8) 7(-137.8,-9.9) 8(-137.8,-29.6) 9(-137.8,-49.2) 10(-137.8,-68.9) 11(-137.8,-88.6) 12(-137.8,-108.3) 25(137.8,-108.3) 26(137.8,-88.6) 27(137.8,-68.9) 28(137.8,-49.2) 29(137.8,-29.6) 30(137.8,-9.9) 31(137.8,9.8) 32(137.8,29.5) 33(137.8,49.2) 34(137.8,68.9) 35(137.8,88.6) 36(137.8,108.2)
  oval 11x39.4 smd paste+0 mask+2: 13(-108.3,-137.8) 14(-88.6,-137.8) 15(-68.9,-137.8) 16(-49.2,-137.8) 17(-29.5,-137.8) 18(-9.9,-137.8) 19(9.8,-137.8) 20(29.5,-137.8) 21(49.2,-137.8) 22(68.9,-137.8) 23(88.6,-137.8) 24(108.3,-137.8) 37(108.3,137.8) 38(88.6,137.8) 39(68.9,137.8) 40(49.2,137.8) 41(29.5,137.8) 42(9.8,137.8) 43(-9.9,137.8) 44(-29.5,137.8) 45(-49.2,137.8) 46(-68.9,137.8) 47(-88.6,137.8) 48(-108.3,137.8)
  rect 161.4x161.4 smd paste+0 mask+2: 49(0,0)
  silkscreen extent -173,-147 147,147
QFN-104_L10.0-W10.0-P0.35-TL-EP7.5 [mil]
  rect 25.6x5.9 smd paste-3937 mask+2: 1(-196.9,172.3) 2(-196.9,158.5) 3(-196.9,144.7) 4(-196.9,130.9) 5(-196.9,117.2) 6(-196.9,103.4) 7(-196.9,89.6) 8(-196.9,75.8) 9(-196.9,62.1) 10(-196.9,48.3) 11(-196.9,34.5) 12(-196.9,20.7) 13(-196.9,6.9) 14(-196.9,-6.8) 15(-196.9,-20.6) 16(-196.9,-34.4) 17(-196.9,-48.2) 18(-196.9,-62) 19(-196.9,-75.7) 20(-196.9,-89.5) 21(-196.9,-103.3) 22(-196.9,-117.1) 23(-196.9,-130.9) 24(-196.9,-144.6) 25(-196.9,-158.4) 26(-196.9,-172.2) 53(196.8,-172.2) 54(196.8,-158.4) 55(196.8,-144.6) 56(196.8,-130.9) 57(196.8,-117.1) 58(196.8,-103.3) 59(196.8,-89.5) 60(196.8,-75.7) 61(196.8,-62) 62(196.8,-48.2) 63(196.8,-34.4) 64(196.8,-20.6) 65(196.8,-6.8) 66(196.8,6.9) 67(196.8,20.7) 68(196.8,34.5) 69(196.8,48.3) 70(196.8,62.1) 71(196.8,75.8) 72(196.8,89.6) 73(196.8,103.4) 74(196.8,117.2) 75(196.8,131) 76(196.8,144.7) 77(196.8,158.5) 78(196.8,172.3)
  rect 5.9x25.6 smd paste-3937 mask+2: 27(-172.2,-196.8) 28(-158.5,-196.8) 29(-144.7,-196.8) 30(-130.9,-196.8) 31(-117.1,-196.8) 32(-103.4,-196.8) 33(-89.6,-196.8) 34(-75.8,-196.8) 35(-62,-196.8) 36(-48.2,-196.8) 37(-34.5,-196.8) 38(-20.7,-196.8) 39(-6.9,-196.8) 40(6.9,-196.8) 41(20.7,-196.8) 42(34.4,-196.8) 43(48.2,-196.8) 44(62,-196.8) 45(75.8,-196.8) 46(89.6,-196.8) 47(103.3,-196.8) 48(117.1,-196.8) 49(130.9,-196.8) 50(144.7,-196.8) 51(158.5,-196.8) 52(172.2,-196.8) 79(172.2,196.9) 80(158.5,196.9) 81(144.7,196.9) 82(130.9,196.9) 83(117.1,196.9) 84(103.3,196.9) 85(89.6,196.9) 86(75.8,196.9) 87(62,196.9) 88(48.2,196.9) 89(34.4,196.9) 90(20.7,196.9) 91(6.9,196.9) 92(-6.9,196.9) 93(-20.7,196.9) 94(-34.5,196.9) 95(-48.2,196.9) 96(-62,196.9) 97(-75.8,196.9) 98(-89.6,196.9) 99(-103.4,196.9) 100(-117.1,196.9) 101(-130.9,196.9) 102(-144.7,196.9) 103(-158.5,196.9) 104(-172.2,196.9)
  rect 295.3x295.3 smd paste-3937 mask+2: 105(0,0)
  silkscreen extent -236,-200 200,200
R0402#1 [mil]
  rect 22.3x21.3 smd paste-3937 mask+2: 1(-17,0) 2(17,0)
  silkscreen extent -37,-20 37,20
R0402#2 [mil]
  rect 22.3x21.3 smd paste-3937 mask+2: 1(-17,0) 2(17.1,0)
  silkscreen extent -37,-20 37,20
R0402#3 [mil]
  rect 22.3x21.3 smd paste-3937 mask+2: 1(-17.1,0) 2(17,0)
  silkscreen extent -37,-20 37,20
R0603#1 [mil]
  rect 31.8x34 smd paste-3937 mask+2: 1(-29.6,0) 2(29.7,0)
  silkscreen extent -54,-26 55,26
R0603#2 [mil]
  rect 31.8x34 smd paste-3937 mask+2: 1(-29.7,0) 2(29.6,0)
  silkscreen extent -55,-26 54,26
R0603#3 [mil]
  rect 31.8x34 smd paste-3937 mask+2: 1(-29.7,0) 2(29.7,0)
  silkscreen extent -54,-26 54,26
RJ45-TH_HR911105A [mil]
  rect 63x63 hole 39.4: 1(-175.2,171.4)
  round 63 hole 39.4: 2(-125.2,271.4) 3(-75.2,171.4) 4(-25.2,271.4) 5(24.8,171.4) 6(74.8,271.4) 7(124.8,171.4) 8(174.8,271.4)
  round 70.9 hole 43.3: 9(-260.8,-271.5) 10(-160.8,-271.5) 11(160.9,-271.5) 12(260.9,-271.5)
  round 98.4 hole 70.9: SH1(-304.9,41.5) SH2(305,41.5)
  Board Outline Layer lines w0.1: 226.8,-143.5 234,-142.9 241,-141.6 247.8,-139.4 254.4,-136.5 260.6,-133 266.3,-128.7 271.6,-123.9 276.3,-118.5 280.4,-112.6 283.8,-106.3 286.5,-99.7 288.4,-92.8 289.6,-85.7 290,-78.6 289.6,-71.4 288.4,-64.4 286.5,-57.5 283.8,-50.9 280.4,-44.6 276.3,-38.7 271.6,-33.3 266.3,-28.4 260.6,-24.2 254.4,-20.6 247.8,-17.7 241,-15.6 234,-14.2 226.8,-13.6 219.7,-13.8 212.6,-14.8 205.6,-16.6 198.9,-19.1 192.6,-22.3 186.6,-26.2 181,-30.8 176.1,-35.9 171.7,-41.6 167.9,-47.7 164.9,-54.1 162.5,-60.9 161,-67.9 160.2,-75 160.2,-82.2 161,-89.3 162.5,-96.3 164.9,-103 167.9,-109.5 171.7,-115.6 176.1,-121.2 181,-126.4 186.6,-130.9 192.6,-134.8 198.9,-138.1 205.6,-140.6 212.6,-142.3 219.7,-143.3 226.8,-143.5 ; -223.2,-143.5 -216,-142.9 -209,-141.6 -202.2,-139.4 -195.6,-136.5 -189.4,-133 -183.7,-128.7 -178.4,-123.9 -173.7,-118.5 -169.6,-112.6 -166.2,-106.3 -163.5,-99.7 -161.6,-92.8 -160.4,-85.7 -160,-78.6 -160.4,-71.4 -161.6,-64.4 -163.5,-57.5 -166.2,-50.9 -169.6,-44.6 -173.7,-38.7 -178.4,-33.3 -183.7,-28.4 -189.4,-24.2 -195.6,-20.6 -202.2,-17.7 -209,-15.6 -216,-14.2 -223.2,-13.6 -230.3,-13.8 -237.4,-14.8 -244.4,-16.6 -251.1,-19.1 -257.4,-22.3 -263.4,-26.2 -269,-30.8 -273.9,-35.9 -278.3,-41.6 -282.1,-47.7 -285.1,-54.1 -287.5,-60.9 -289,-67.9 -289.8,-75 -289.8,-82.2 -289,-89.3 -287.5,-96.3 -285.1,-103 -282.1,-109.5 -278.3,-115.6 -273.9,-121.2 -269,-126.4 -263.4,-130.9 -257.4,-134.8 -251.1,-138.1 -244.4,-140.6 -237.4,-142.3 -230.3,-143.3 -223.2,-143.5
  Board Outline Layer region: -160,-78.6 -160.4,-85.7 -161.6,-92.8 -163.5,-99.7 -166.2,-106.3 -169.6,-112.6 -173.7,-118.5 -178.4,-123.9 -183.7,-128.7 -189.4,-133 -195.6,-136.5 -202.2,-139.4 -209,-141.6 -216,-142.9 -223.2,-143.5 -230.3,-143.3 -237.4,-142.3 -244.4,-140.6 -251.1,-138.1 -257.4,-134.8 -263.4,-130.9 -269,-126.4 -273.9,-121.2 -278.3,-115.6 -282.1,-109.5 -285.1,-103 -287.5,-96.3 -289,-89.3 -289.8,-82.2 -289.8,-75 -289,-67.9 -287.5,-60.9 -285.1,-54.1 -282.1,-47.7 -278.3,-41.6 -273.9,-35.9 -269,-30.8 -263.4,-26.2 -257.4,-22.3 -251.1,-19.1 -244.4,-16.6 -237.4,-14.8 -230.3,-13.8 -223.2,-13.6 -216,-14.2 -209,-15.6 -202.2,-17.7 -195.6,-20.6 -189.4,-24.2 -183.7,-28.4 -178.4,-33.3 -173.7,-38.7 -169.6,-44.6 -166.2,-50.9 -163.5,-57.5 -161.6,-64.4 -160.4,-71.4
  Board Outline Layer region: -160,-78.6 -160.4,-85.7 -161.6,-92.8 -163.5,-99.7 -166.2,-106.3 -169.6,-112.6 -173.7,-118.5 -178.4,-123.9 -183.7,-128.7 -189.4,-133 -195.6,-136.5 -202.2,-139.4 -209,-141.6 -216,-142.9 -223.2,-143.5 -230.3,-143.3 -237.4,-142.3 -244.4,-140.6 -251.1,-138.1 -257.4,-134.8 -263.4,-130.9 -269,-126.4 -273.9,-121.2 -278.3,-115.6 -282.1,-109.5 -285.1,-103 -287.5,-96.3 -289,-89.3 -289.8,-82.2 -289.8,-75 -289,-67.9 -287.5,-60.9 -285.1,-54.1 -282.1,-47.7 -278.3,-41.6 -273.9,-35.9 -269,-30.8 -263.4,-26.2 -257.4,-22.3 -251.1,-19.1 -244.4,-16.6 -237.4,-14.8 -230.3,-13.8 -223.2,-13.6 -216,-14.2 -209,-15.6 -202.2,-17.7 -195.6,-20.6 -189.4,-24.2 -183.7,-28.4 -178.4,-33.3 -173.7,-38.7 -169.6,-44.6 -166.2,-50.9 -163.5,-57.5 -161.6,-64.4 -160.4,-71.4
  Board Outline Layer region: 290,-78.6 289.6,-85.7 288.4,-92.8 286.5,-99.7 283.8,-106.3 280.4,-112.6 276.3,-118.5 271.6,-123.9 266.3,-128.7 260.6,-133 254.4,-136.5 247.8,-139.4 241,-141.6 234,-142.9 226.8,-143.5 219.7,-143.3 212.6,-142.3 205.6,-140.6 198.9,-138.1 192.6,-134.8 186.6,-130.9 181,-126.4 176.1,-121.2 171.7,-115.6 167.9,-109.5 164.9,-103 162.5,-96.3 161,-89.3 160.2,-82.2 160.2,-75 161,-67.9 162.5,-60.9 164.9,-54.1 167.9,-47.7 171.7,-41.6 176.1,-35.9 181,-30.8 186.6,-26.2 192.6,-22.3 198.9,-19.1 205.6,-16.6 212.6,-14.8 219.7,-13.8 226.8,-13.6 234,-14.2 241,-15.6 247.8,-17.7 254.4,-20.6 260.6,-24.2 266.3,-28.4 271.6,-33.3 276.3,-38.7 280.4,-44.6 283.8,-50.9 286.5,-57.5 288.4,-64.4 289.6,-71.4
  Board Outline Layer region: 290,-78.6 289.6,-85.7 288.4,-92.8 286.5,-99.7 283.8,-106.3 280.4,-112.6 276.3,-118.5 271.6,-123.9 266.3,-128.7 260.6,-133 254.4,-136.5 247.8,-139.4 241,-141.6 234,-142.9 226.8,-143.5 219.7,-143.3 212.6,-142.3 205.6,-140.6 198.9,-138.1 192.6,-134.8 186.6,-130.9 181,-126.4 176.1,-121.2 171.7,-115.6 167.9,-109.5 164.9,-103 162.5,-96.3 161,-89.3 160.2,-82.2 160.2,-75 161,-67.9 162.5,-60.9 164.9,-54.1 167.9,-47.7 171.7,-41.6 176.1,-35.9 181,-30.8 186.6,-26.2 192.6,-22.3 198.9,-19.1 205.6,-16.6 212.6,-14.8 219.7,-13.8 226.8,-13.6 234,-14.2 241,-15.6 247.8,-17.7 254.4,-20.6 260.6,-24.2 266.3,-28.4 271.6,-33.3 276.3,-38.7 280.4,-44.6 283.8,-50.9 286.5,-57.5 288.4,-64.4 289.6,-71.4
  Multi-Layer board cut-out: -160,-78.6 -160.4,-85.7 -161.6,-92.8 -163.5,-99.7 -166.2,-106.3 -169.6,-112.6 -173.7,-118.5 -178.4,-123.9 -183.7,-128.7 -189.4,-133 -195.6,-136.5 -202.2,-139.4 -209,-141.6 -216,-142.9 -223.2,-143.5 -230.3,-143.3 -237.4,-142.3 -244.4,-140.6 -251.1,-138.1 -257.4,-134.8 -263.4,-130.9 -269,-126.4 -273.9,-121.2 -278.3,-115.6 -282.1,-109.5 -285.1,-103 -287.5,-96.3 -289,-89.3 -289.8,-82.2 -289.8,-75 -289,-67.9 -287.5,-60.9 -285.1,-54.1 -282.1,-47.7 -278.3,-41.6 -273.9,-35.9 -269,-30.8 -263.4,-26.2 -257.4,-22.3 -251.1,-19.1 -244.4,-16.6 -237.4,-14.8 -230.3,-13.8 -223.2,-13.6 -216,-14.2 -209,-15.6 -202.2,-17.7 -195.6,-20.6 -189.4,-24.2 -183.7,-28.4 -178.4,-33.3 -173.7,-38.7 -169.6,-44.6 -166.2,-50.9 -163.5,-57.5 -161.6,-64.4 -160.4,-71.4
  Multi-Layer board cut-out: 290,-78.6 289.6,-85.7 288.4,-92.8 286.5,-99.7 283.8,-106.3 280.4,-112.6 276.3,-118.5 271.6,-123.9 266.3,-128.7 260.6,-133 254.4,-136.5 247.8,-139.4 241,-141.6 234,-142.9 226.8,-143.5 219.7,-143.3 212.6,-142.3 205.6,-140.6 198.9,-138.1 192.6,-134.8 186.6,-130.9 181,-126.4 176.1,-121.2 171.7,-115.6 167.9,-109.5 164.9,-103 162.5,-96.3 161,-89.3 160.2,-82.2 160.2,-75 161,-67.9 162.5,-60.9 164.9,-54.1 167.9,-47.7 171.7,-41.6 176.1,-35.9 181,-30.8 186.6,-26.2 192.6,-22.3 198.9,-19.1 205.6,-16.6 212.6,-14.8 219.7,-13.8 226.8,-13.6 234,-14.2 241,-15.6 247.8,-17.7 254.4,-20.6 260.6,-24.2 266.3,-28.4 271.6,-33.3 276.3,-38.7 280.4,-44.6 283.8,-50.9 286.5,-57.5 288.4,-64.4 289.6,-71.4
  silkscreen extent -317,-509 317,342
SO-16_L10.3-W4.4-P1.27-LS7.0-BL [mil]
  oval 22x79.5 smd: 1(-175,-118.5) 2(-125,-118.5) 3(-75,-118.5) 4(-25,-118.5) 5(25,-118.5) 6(75,-118.5) 7(125,-118.5) 8(175,-118.5) 9(175,118.5) 10(125,118.5) 11(75,118.5) 12(25,118.5) 13(-25,118.5) 14(-75,118.5) 15(-125,118.5) 16(-175,118.5)
  silkscreen extent -227,-122 205,71
SOT-23-5_L2.9-W1.6-P0.95-LS2.8-BL [mil]
  rect 23.6x39.4 smd paste+0 mask+2: 1(-37.4,-43.3) 2(0,-43.3) 3(37.4,-43.3) 4(37.4,43.3) 5(-37.4,43.3)
  silkscreen extent -60,-28 55,35
SOT-23-5_L3.0-W1.7-P0.95-LS2.8-BR#1 [mil]
  rect 43.3x23.6 smd: 1(51.2,-37.4) 2(51.2,0) 3(51.2,37.4) 4(-51.1,37.4) 5(-51.1,-37.4)
  silkscreen extent -35,-61 36,61
SOT-23-5_L3.0-W1.7-P0.95-LS2.8-BR#2 [mil]
  rect 43.3x23.6 smd: 1(51.2,-37.4) 2(51.2,0) 3(51.2,37.4) 4(-51.2,37.4) 5(-51.2,-37.4)
  silkscreen extent -36,-61 35,61
SOT-23-6_L2.9-W1.6-P0.95-LS2.8-BR [mil]
  rect 43.3x23.6 smd paste+0 mask+2: 1(53.1,-37.41) 2(53.17,0) 3(53.1,37.41) 4(-53.1,37.41) 5(-53.17,0) 6(-53.17,-37.34)
  silkscreen extent -35,-70 60,61
SOT-563-6_L1.6-W1.2-P0.50-LS1.6-BL [mil]
  rect 11x26.8 smd: 1(-19.7,-25.2) 2(0,-25.2) 3(19.7,-25.2) 4(19.7,25.2) 5(0,25.2) 6(-19.7,25.2)
  silkscreen extent -40,-40 34,27
TF-SMD_XKTF-1307-18 [mil]
  rect 31.5x59.1 smd: 1(126,-61) 2(82.7,-61) 3(39.4,-61) 4(-3.9,-61) 5(-47.2,-61) 6(-90.5,-61) 7(-133.8,-61) 8(-177.1,-61)
  rect 57.1x78.7 smd: 9(-270.6,163.4) 10(-270.6,-163.4) 11(270.7,-163.4) 12(270.7,163.4)
  silkscreen extent -268,-260 268,311
TQFN-16_L3.0-W3.0-P0.50-BL-EP1.7#1 [mil]
  rect 9.8x29.5 smd paste-3937 mask+2: 1(-29.5,-57.1) 2(-9.8,-57.1) 3(9.9,-57.1) 4(29.6,-57.1) 9(29.5,57.1) 10(9.8,57.1) 11(-9.8,57.1) 12(-29.5,57.1)
  rect 29.5x9.8 smd paste-3937 mask+2: 5(57.1,-29.5) 6(57.1,-9.8) 7(57.1,9.9) 8(57.1,29.5) 13(-57.1,29.5) 14(-57.1,9.9) 15(-57.1,-9.8) 16(-57.1,-29.5)
  rect 66.9x66.9 smd paste-3937 mask+2: 17(0,0)
  silkscreen extent -59,-86 59,59
TQFN-16_L3.0-W3.0-P0.50-BL-EP1.7#2 [mil]
  rect 9.8x29.5 smd paste-3937 mask+2: 1(-29.5,-57) 2(-9.8,-57) 3(9.9,-57) 4(29.6,-57) 9(29.5,57.1) 10(9.8,57.1) 11(-9.9,57.1) 12(-29.5,57.1)
  rect 29.5x9.8 smd paste-3937 mask+2: 5(57.1,-29.5) 6(57.1,-9.8) 7(57.1,9.9) 8(57.1,29.6) 13(-57.1,29.6) 14(-57.1,9.9) 15(-57.1,-9.8) 16(-57.1,-29.5)
  rect 66.9x66.9 smd paste-3937 mask+2: 17(0,0)
  silkscreen extent -59,-86 59,59
USB-C-SMD_HX-TYPE-C-16P-L8.35 [mil]
  oval 39.4x82.7 hole 23.6 slot 66.9 at 90 deg paste+0 mask+2: 1(-170.1,64) 2(170,64)
  oval 39.4x70.9 hole 23.6 slot 55.1 at 90 deg paste+0 mask+2: 3(-170.1,-100.5) 4(170,-100.5)
  rect 20.9x57.1 smd paste-3937 mask+2: A1B12(-126,100.4) A4B9(-94.5,100.4) B1A12(125.9,100.4) B4A9(94.5,100.4)
  rect 11.8x57.1 smd paste-3937 mask+2: A5(-49.2,100.4) A6(-9.9,100.4) A7(9.8,100.4) A8(49.2,100.4) B5(68.9,100.4) B6(29.5,100.4) B7(-29.6,100.4) B8(-68.9,100.4)
  Board Outline Layer lines w0.1: 112.4,30.6 115.5,30.8 118.6,31.7 121.4,33.3 123.7,35.5 125.5,38.2 126.6,41.2 126.9,44.3 126.6,47.5 125.5,50.5 123.7,53.2 121.4,55.4 118.6,57 115.5,57.9 112.4,58.1 109.2,57.5 106.3,56.3 103.7,54.4 101.6,51.9 100.2,49.1 99.5,45.9 99.5,42.7 100.2,39.6 101.6,36.8 103.7,34.3 106.3,32.4 109.2,31.1 112.4,30.6 ; -114,30.6 -110.8,30.8 -107.8,31.7 -105,33.3 -102.7,35.5 -100.9,38.2 -99.8,41.2 -99.4,44.4 -99.8,47.6 -100.9,50.6 -102.7,53.2 -105,55.4 -107.8,57 -110.8,58 -114,58.1 -117.2,57.6 -120.1,56.3 -122.7,54.4 -124.7,52 -126.2,49.1 -126.9,46 -126.9,42.8 -126.2,39.7 -124.7,36.8 -122.7,34.4 -120.1,32.5 -117.2,31.2 -114,30.6
  Board Outline Layer region: 126.9,44.3 126.6,41.2 125.5,38.2 123.7,35.5 121.4,33.3 118.6,31.7 115.5,30.8 112.4,30.6 109.2,31.1 106.3,32.4 103.7,34.3 101.6,36.8 100.2,39.6 99.5,42.7 99.5,45.9 100.2,49.1 101.6,51.9 103.7,54.4 106.3,56.3 109.2,57.5 112.4,58.1 115.5,57.9 118.6,57 121.4,55.4 123.7,53.2 125.5,50.5 126.6,47.5
  Board Outline Layer region: 126.9,44.3 126.6,41.2 125.5,38.2 123.7,35.5 121.4,33.3 118.6,31.7 115.5,30.8 112.4,30.6 109.2,31.1 106.3,32.4 103.7,34.3 101.6,36.8 100.2,39.6 99.5,42.7 99.5,45.9 100.2,49.1 101.6,51.9 103.7,54.4 106.3,56.3 109.2,57.5 112.4,58.1 115.5,57.9 118.6,57 121.4,55.4 123.7,53.2 125.5,50.5 126.6,47.5
  Board Outline Layer region: -99.4,44.4 -99.8,41.2 -100.9,38.2 -102.7,35.5 -105,33.3 -107.8,31.7 -110.8,30.8 -114,30.6 -117.2,31.2 -120.1,32.5 -122.7,34.4 -124.7,36.8 -126.2,39.7 -126.9,42.8 -126.9,46 -126.2,49.1 -124.7,52 -122.7,54.4 -120.1,56.3 -117.2,57.6 -114,58.1 -110.8,58 -107.8,57 -105,55.4 -102.7,53.2 -100.9,50.6 -99.8,47.6
  Board Outline Layer region: -99.4,44.4 -99.8,41.2 -100.9,38.2 -102.7,35.5 -105,33.3 -107.8,31.7 -110.8,30.8 -114,30.6 -117.2,31.2 -120.1,32.5 -122.7,34.4 -124.7,36.8 -126.2,39.7 -126.9,42.8 -126.9,46 -126.2,49.1 -124.7,52 -122.7,54.4 -120.1,56.3 -117.2,57.6 -114,58.1 -110.8,58 -107.8,57 -105,55.4 -102.7,53.2 -100.9,50.6 -99.8,47.6
  Multi-Layer board cut-out: 126.9,44.3 126.6,41.2 125.5,38.2 123.7,35.5 121.4,33.3 118.6,31.7 115.5,30.8 112.4,30.6 109.2,31.1 106.3,32.4 103.7,34.3 101.6,36.8 100.2,39.6 99.5,42.7 99.5,45.9 100.2,49.1 101.6,51.9 103.7,54.4 106.3,56.3 109.2,57.5 112.4,58.1 115.5,57.9 118.6,57 121.4,55.4 123.7,53.2 125.5,50.5 126.6,47.5
  Multi-Layer board cut-out: -99.4,44.4 -99.8,41.2 -100.9,38.2 -102.7,35.5 -105,33.3 -107.8,31.7 -110.8,30.8 -114,30.6 -117.2,31.2 -120.1,32.5 -122.7,34.4 -124.7,36.8 -126.2,39.7 -126.9,42.8 -126.9,46 -126.2,49.1 -124.7,52 -122.7,54.4 -120.1,56.3 -117.2,57.6 -114,58.1 -110.8,58 -107.8,57 -105,55.4 -102.7,53.2 -100.9,50.6 -99.8,47.6
  silkscreen extent -170,-243 170,14
USON-10_L2.5-W1.0-P0.50-BL#1 [mil]
  rect 9.8x24 smd: 1(-39.4,-16.3) 2(-19.7,-16.3) 4(19.7,-16.3) 5(39.4,-16.3) 6(39.4,16.3) 7(19.7,16.3) 9(-19.7,16.3) 10(-39.4,16.3)
  rect 15x24 smd: 3(0,-16.3) 8(0,16.3)
  silkscreen extent -52,-44 52,23
USON-10_L2.5-W1.0-P0.50-BL#2 [mil]
  rect 9.8x24 smd: 1(-39.3,-16.3) 2(-19.7,-16.3) 4(19.7,-16.3) 5(39.4,-16.3) 6(39.4,16.3) 7(19.7,16.3) 9(-19.7,16.3) 10(-39.3,16.3)
  rect 15x24 smd: 3(0,-16.3) 8(0,16.3)
  silkscreen extent -52,-44 52,23
WSON-8_L6.0-W8.0-P1.27-BL-EP#1 [mil]
  rect 23.6x47.2 smd: 1(-75,-149.6) 2(-25,-149.5) 3(25,-149.5) 4(75,-149.6) 5(75,149.7) 6(25,149.7) 7(-25,149.7) 8(-75,149.7)
  rect 169.3x133.9 smd: 9(0,0.1)
  silkscreen extent -118,-177 118,158
WSON-8_L6.0-W8.0-P1.27-BL-EP#2 [mil]
  rect 23.6x47.2 smd: 1(-75,-149.6) 2(-25,-149.6) 3(25,-149.6) 4(75,-149.6) 5(75,149.6) 6(25,149.6) 7(-25,149.6) 8(-75,149.6)
  rect 169.3x133.9 smd: 9(0,0)
  silkscreen extent -118,-177 118,158

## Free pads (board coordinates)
  round 252 hole 126: 1(6880.1,6095.2) 2(6880.1,8221.2)
  round 160 hole 120: 1(9003.6,8261)
  round 0 smd: 2(8694.1,8260.5)
  round 0 smd far side: 2(8694.1,8261.4)

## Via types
v1: diameter 15.7, hole 11.8, Top Layer to Bottom Layer, 168 vias
v2: diameter 23.6, hole 11.8, Top Layer to Bottom Layer, 139 vias
v3: diameter 19.7, hole 11.8, Top Layer to Bottom Layer, 91 vias
v4: diameter 23.6, hole 15.7, Top Layer to Bottom Layer, 8 vias

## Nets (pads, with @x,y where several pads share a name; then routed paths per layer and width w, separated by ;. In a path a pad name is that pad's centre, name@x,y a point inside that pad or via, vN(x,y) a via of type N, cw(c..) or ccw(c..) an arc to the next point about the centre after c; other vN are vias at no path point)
1V2_SYS: C36.2 C37.2 C38.2 C75.2 C76.2 L3.2 R23.2 R46.2 U6.19 U6.41 U16.1 | length 787.3
  Top Layer w6.1: U6.19@7598.6,7815.7 v1(7598.6,7855.1) C76.2@7598.6,7877.9
  Top Layer w10: U16.1@7352.6,7976.3 7391.3,8015 v2(7407.6,8015) ; C38.2@7391.9,8162.2 C37.2@7470.6,8162.2 ; v2(7537.6,8337.4) 7549.4,8325.6 C36.2@7580.1,8325.6 ; R46.2@7572.9,8276.3 7572.9,8318.4 C36.2@7580.1,8325.6 ; C75.2@7578.9,7478 v1(7578.9,7500.8) U6.41@7578.9,7540.1 ; C36.2@7586,8331.5 C36.2@7580.1,8325.6
  Top Layer w11.8: R23.2@7262.3,8100.8 7361.1,8100.8 v2(7368.2,8093.7)
  VCC1 w10: v2(7407.6,8093.7) 7407.6,8178.7 7539.4,8310.5 v2@7539.4,8335.5
  other v2: 7368.2,8054.3 7407.6,8054.3
3V3_MS: C33.2 C34.2 C35.2 C80.2 C81.2 C82.2 R20.2 R34.2 R35.2 R36.2 R37.2 U6.16 U6.23 U6.44 U7.6 U10.4 U14.1 U15.1 | length 1463.9
  Top Layer w7.9: v2@7280.5,7451.2 7280.5,7436.8 7313,7404.3 7313,7456.7 U15.1@7320,7463.7
  Top Layer w10: U6.23@7519.8,7815.7 v1(7519.8,7855.1) C82.2@7519.8,7877.9 ; C80.2@7637.9,7478 v1(7637.9,7500.8) U6.44@7637.9,7540.1 ; U6.16@7657.6,7815.7 v1(7657.6,7855.1) C81.2@7657.6,7877.9 ; v3(7956.8,6890.5) 7963.4,6897.1 R20.2@7963.4,6925.9
  VCC w10: 7773.8,7841.3 7773.8,7640.5 7826.9,7587.4 7826.9,7457.4 7974.6,7309.8 7974.6,7055.9 7956.8,7038.1 v3(7956.8,6890.5) 7955.6,6890.5 v3(7903.2,6838.2)
  other v2: 7280,7439.8 7280,7475.3 7813.2,8029.3 7852.6,8029.3 7892,8029.3 7813.2,8068.7 7852.6,8068.7 7892,8068.7
  other v3: 7930,6864.4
